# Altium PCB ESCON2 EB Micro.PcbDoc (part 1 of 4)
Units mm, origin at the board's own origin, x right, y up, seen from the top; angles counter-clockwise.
Board outline 75.6 x 72 mm, 8 copper layers (Top Side, Mid Layer 1, Mid Layer 2, Mid Layer 3, Mid Layer 4, Mid Layer 5, Mid Layer 6, Bottom Side), stack 1.555 mm thick; 192 components, 85 nets, 547 pads, 2387 vias.
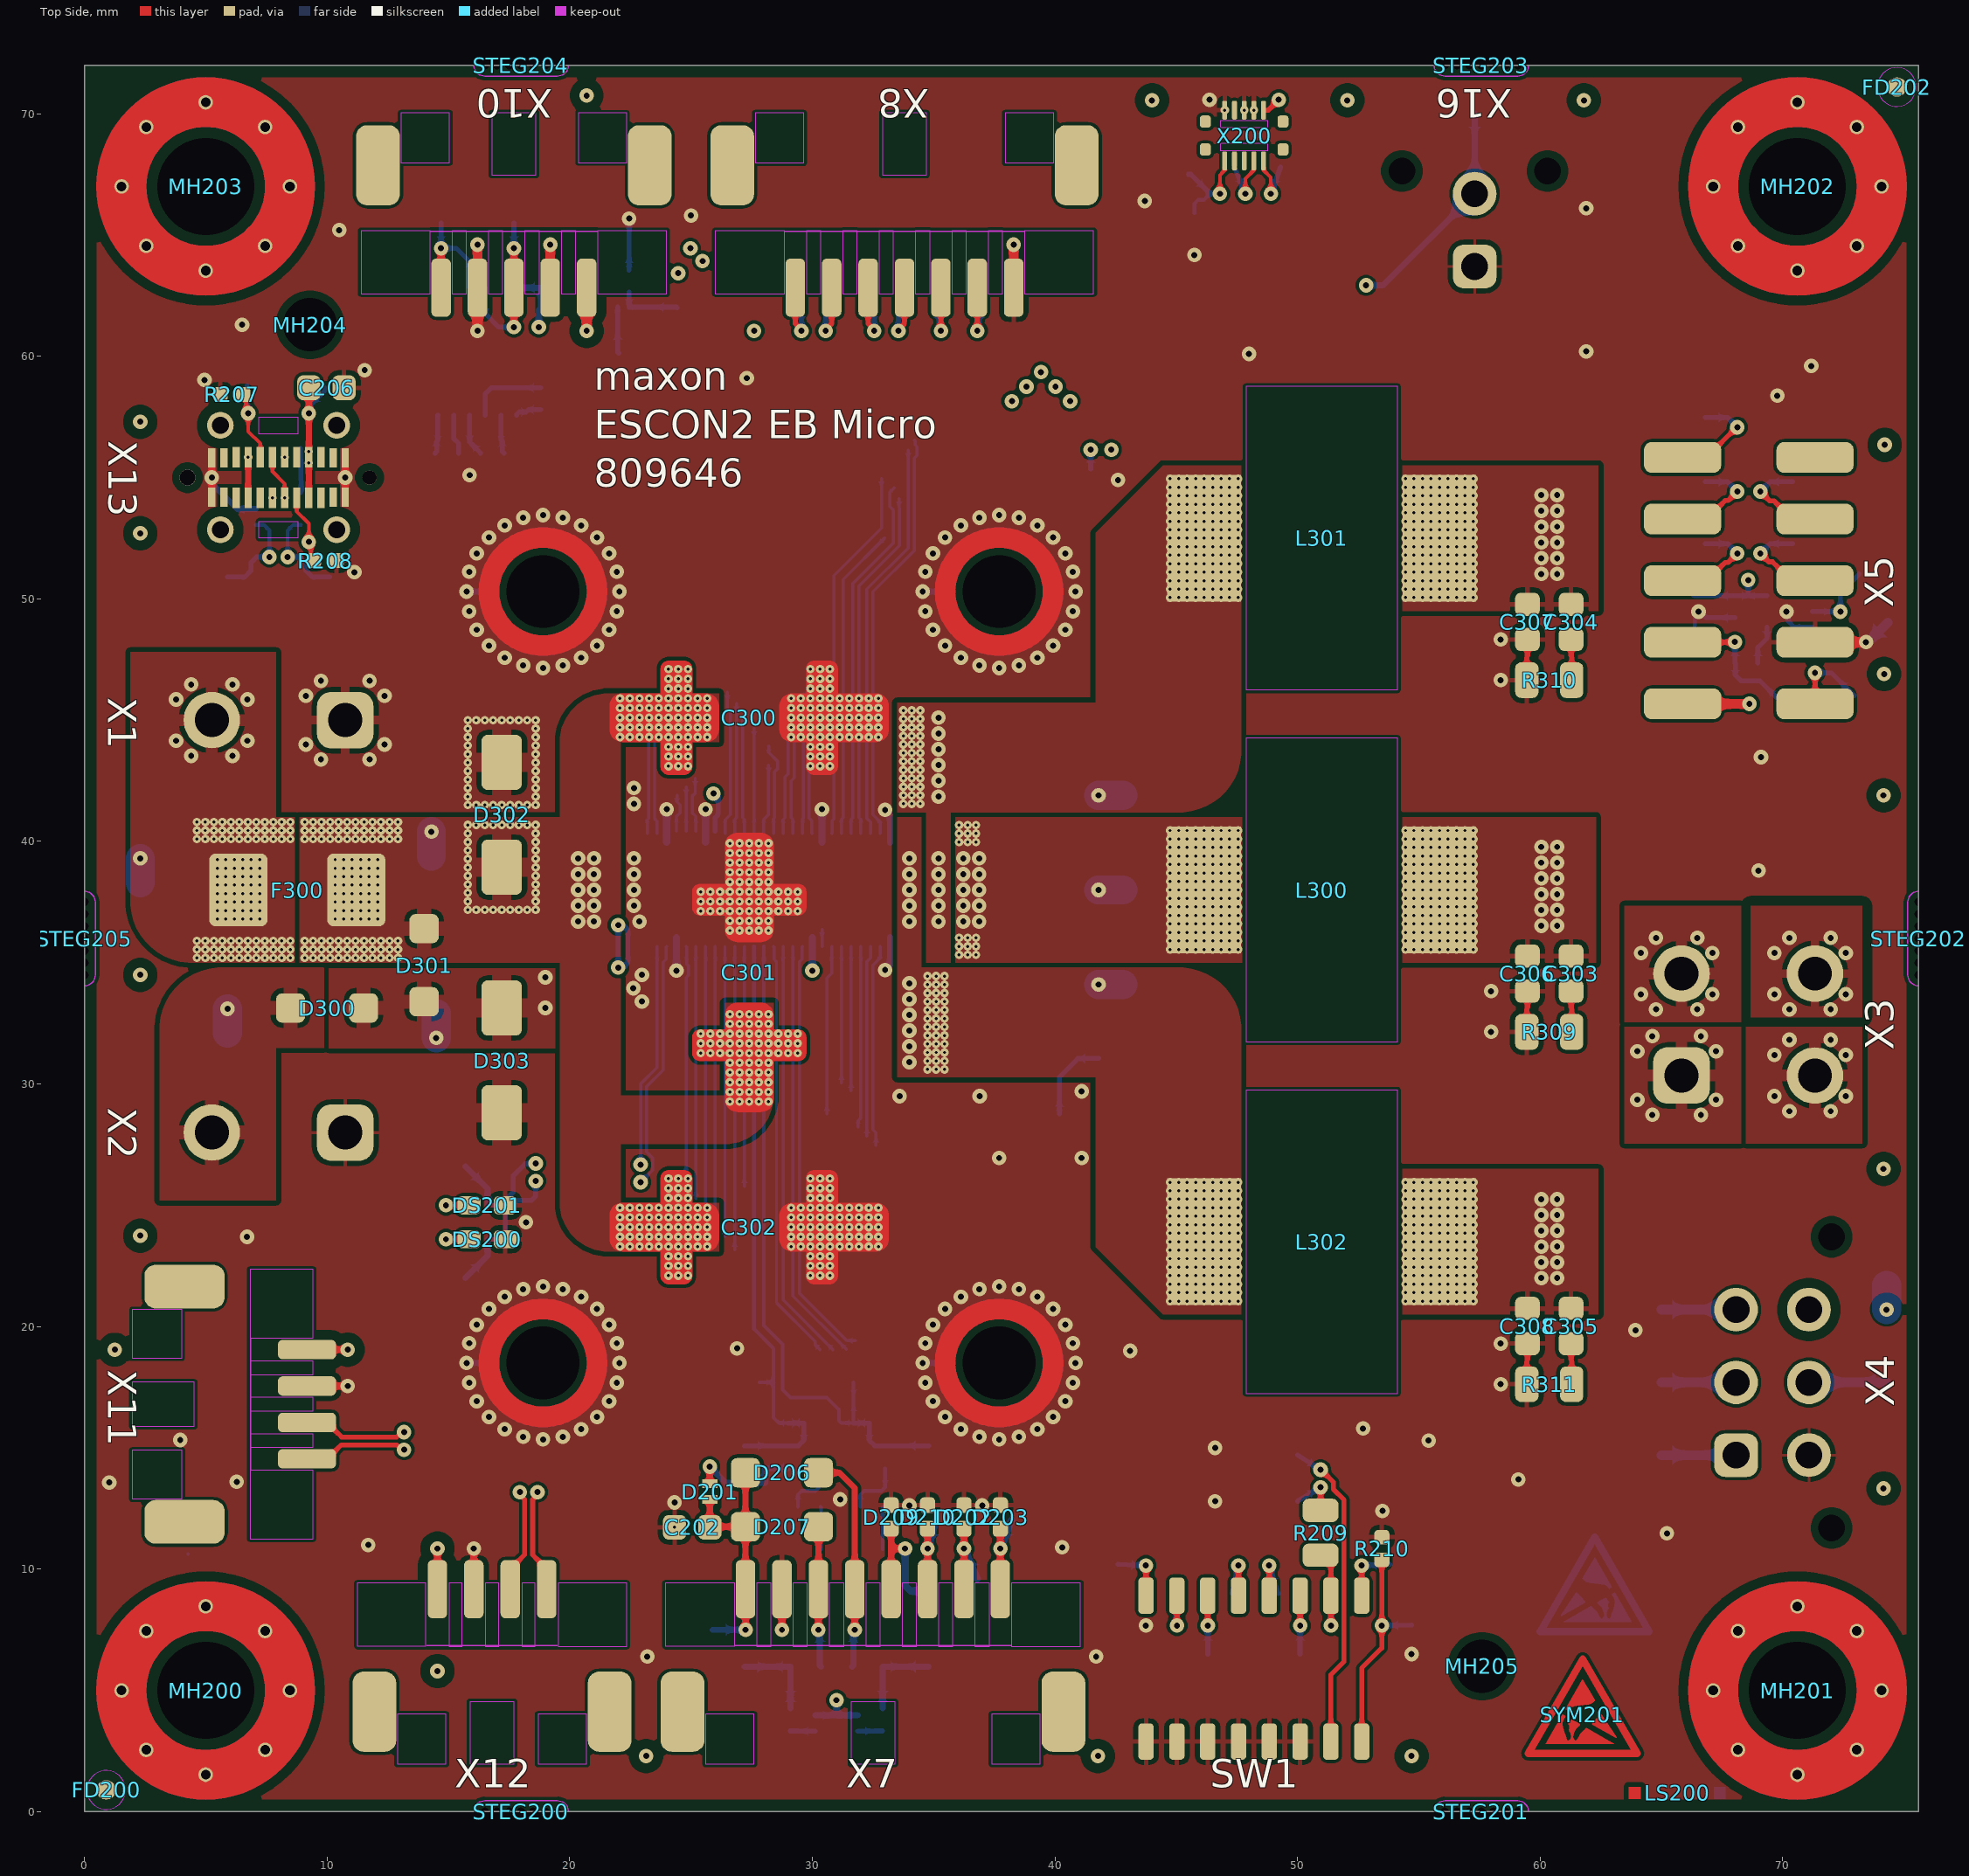
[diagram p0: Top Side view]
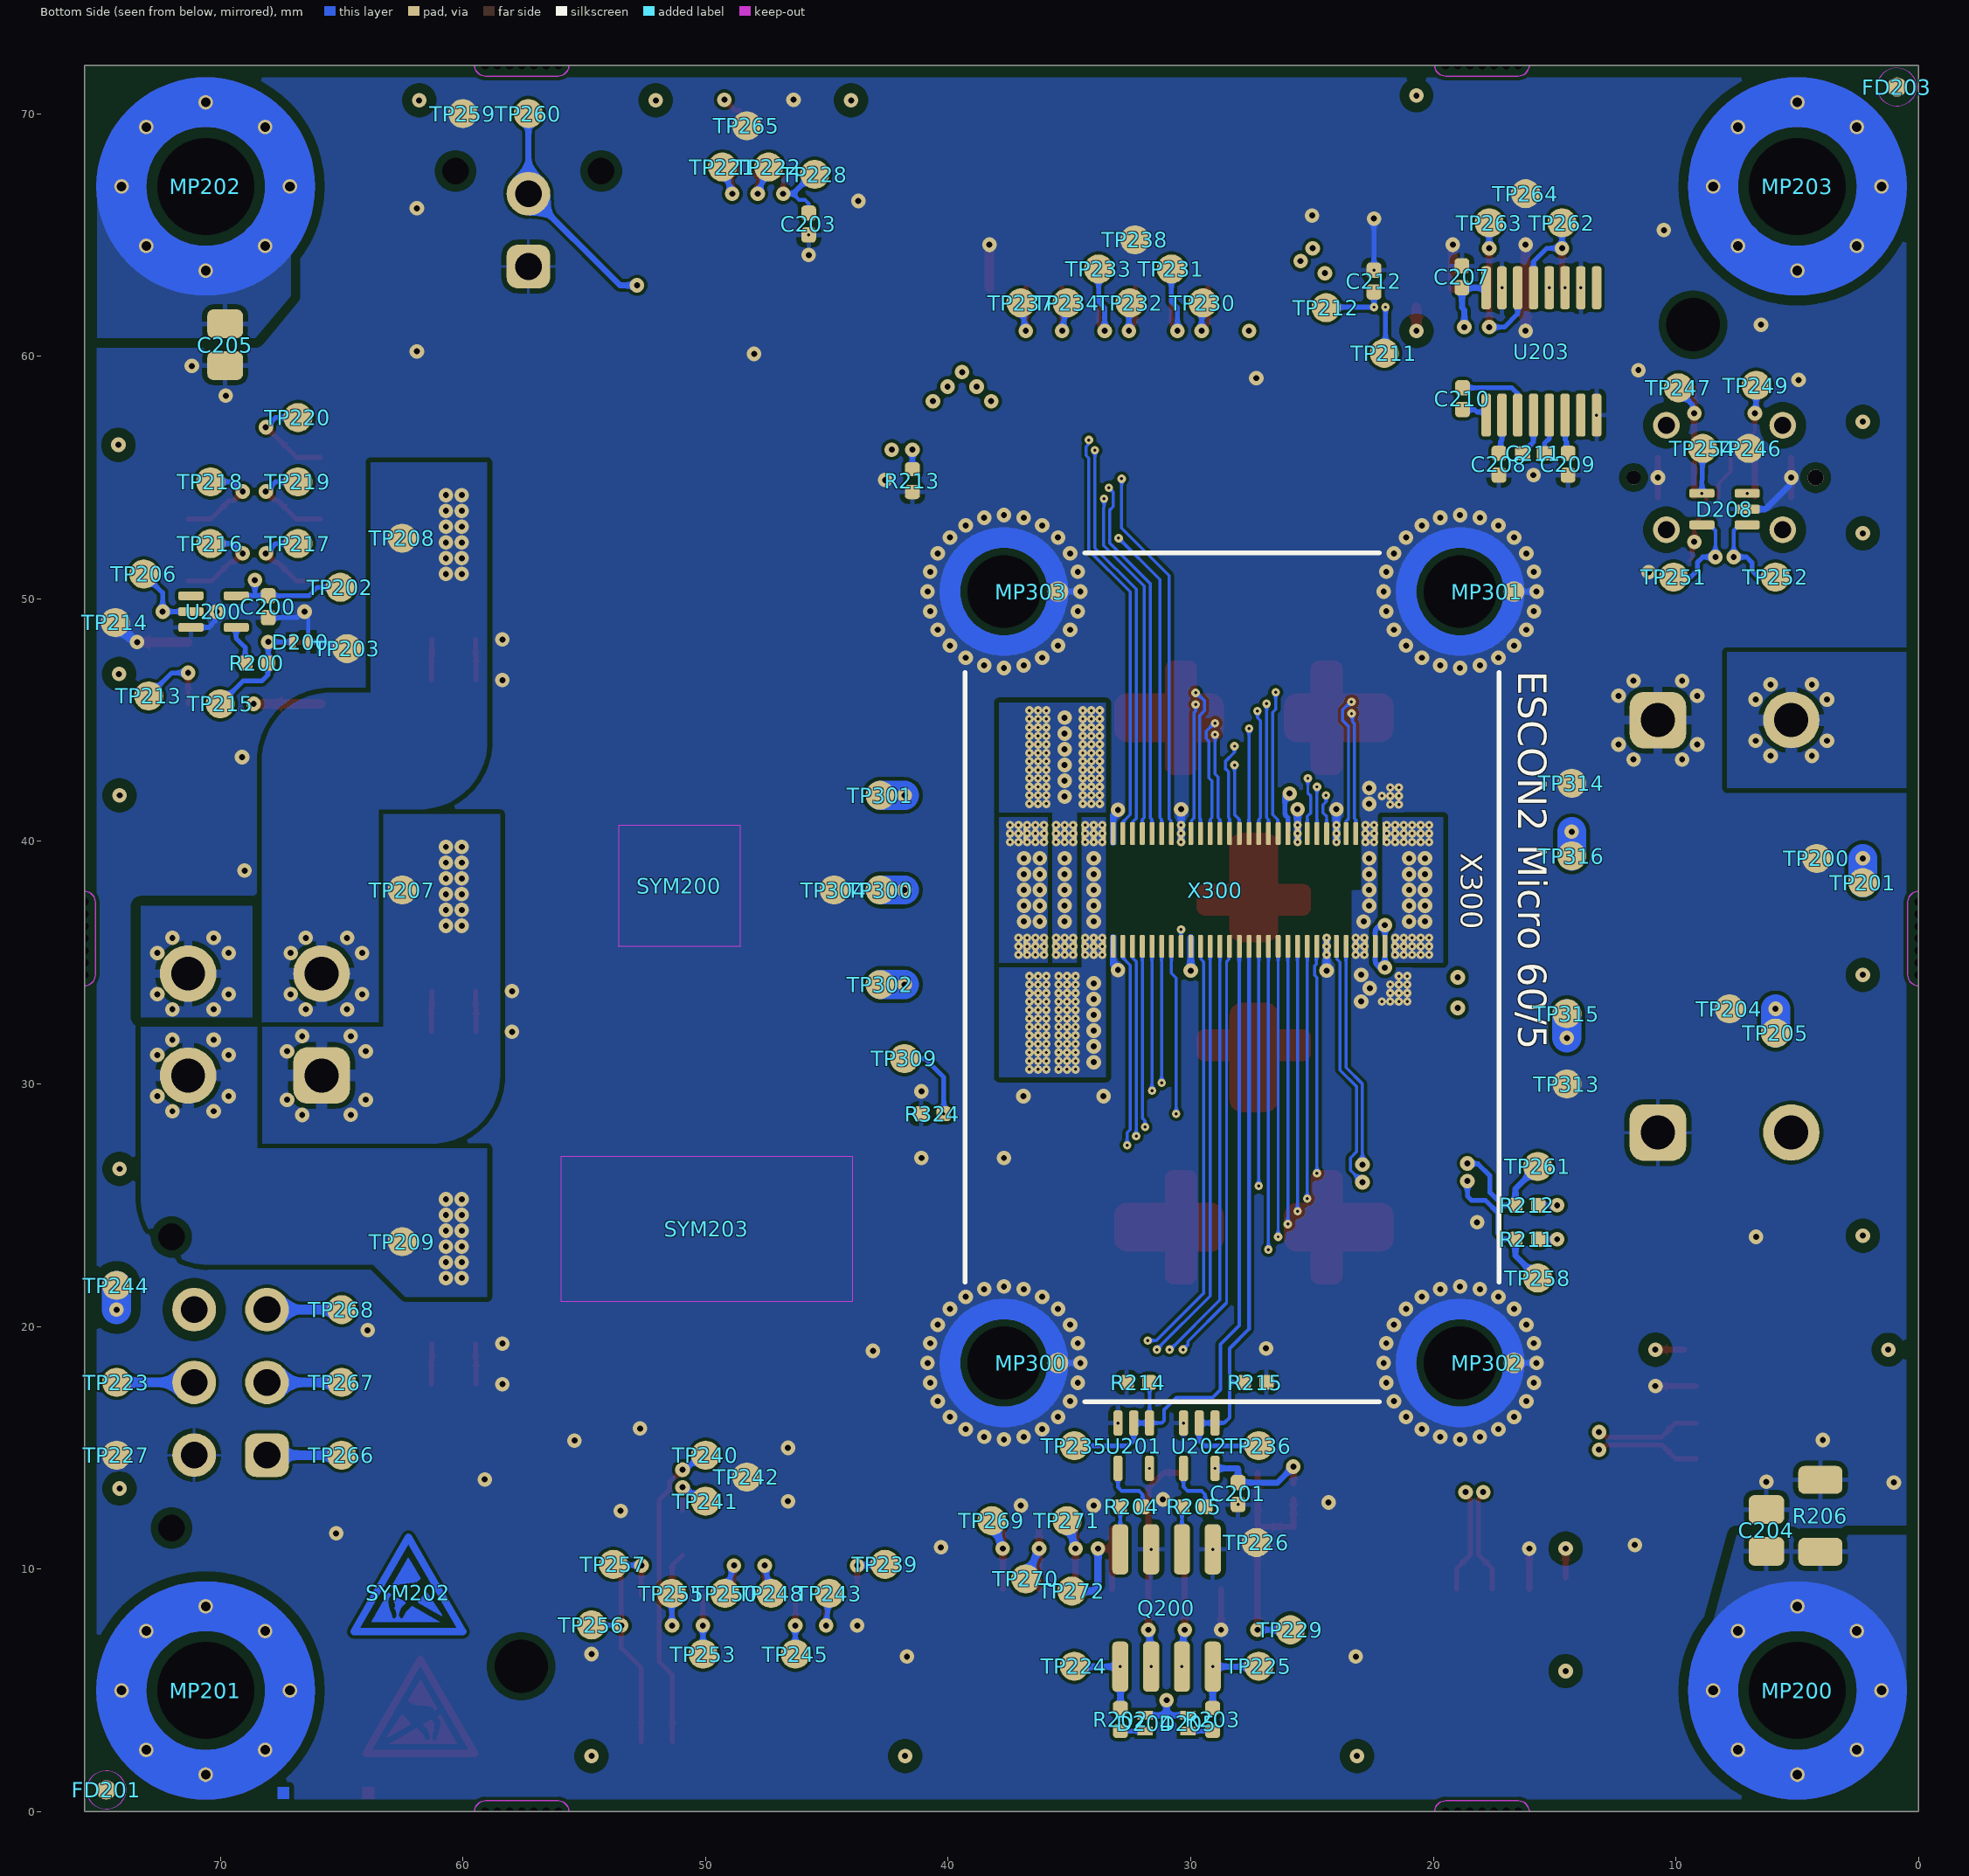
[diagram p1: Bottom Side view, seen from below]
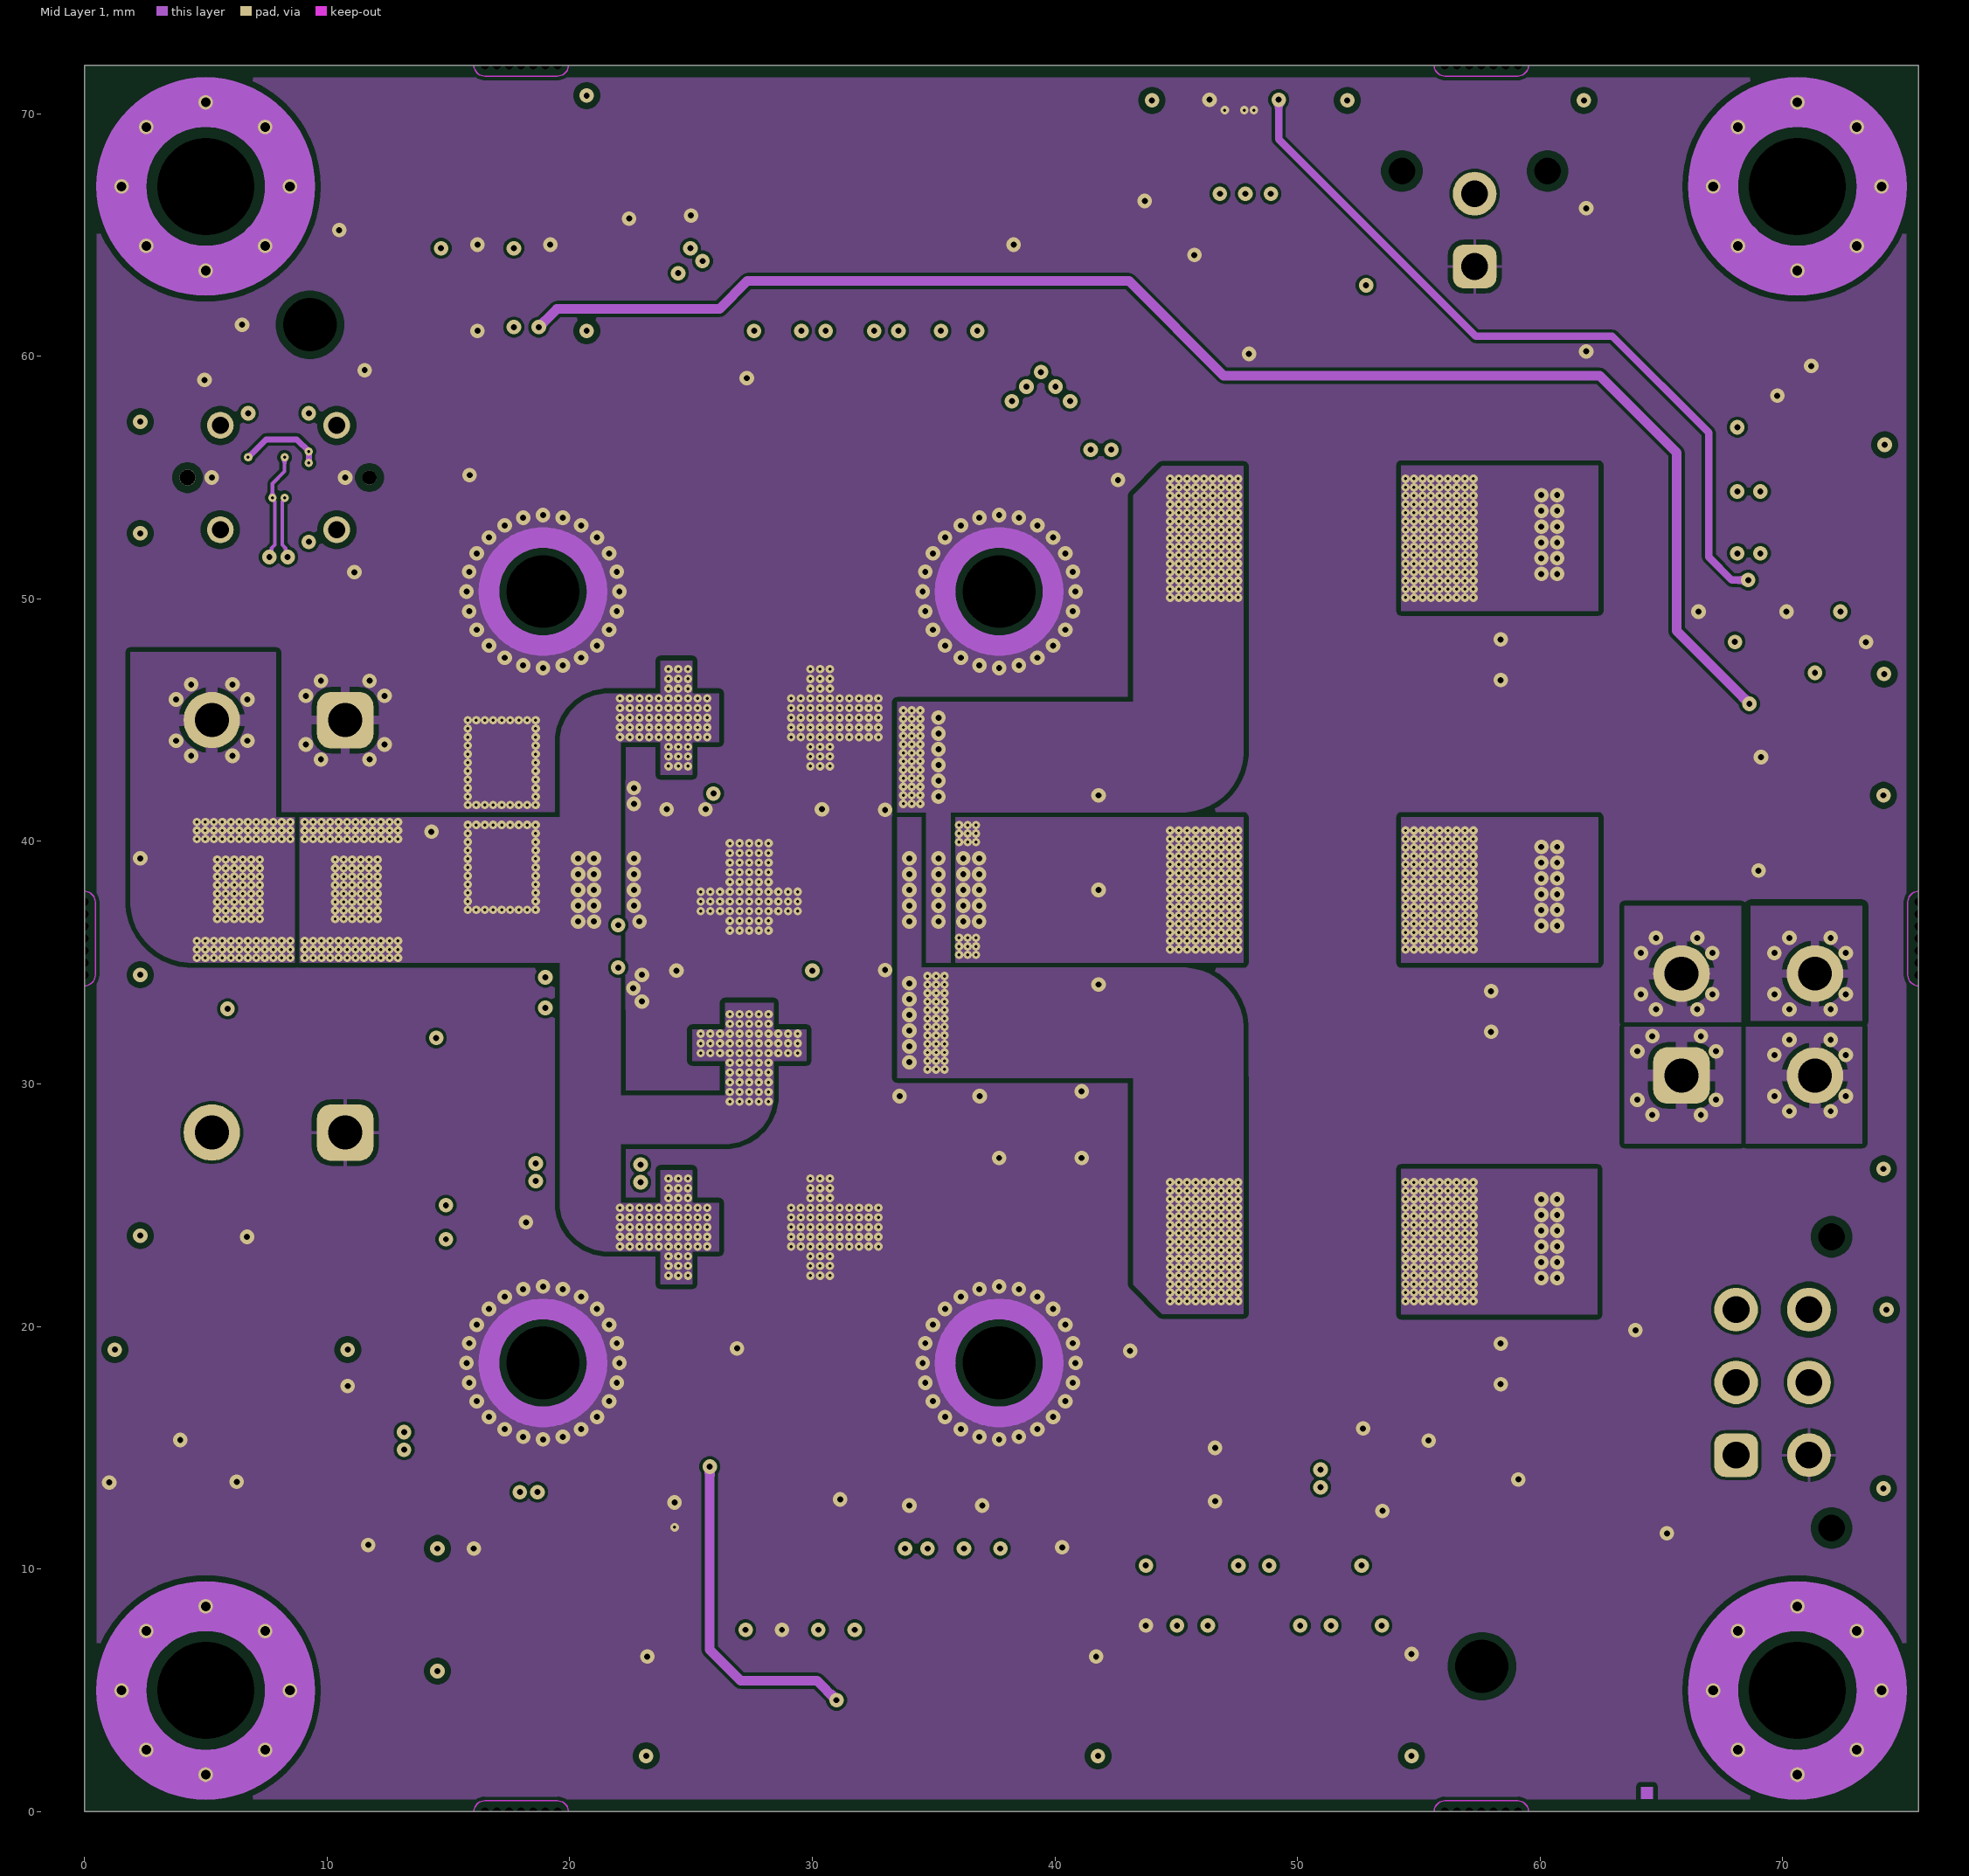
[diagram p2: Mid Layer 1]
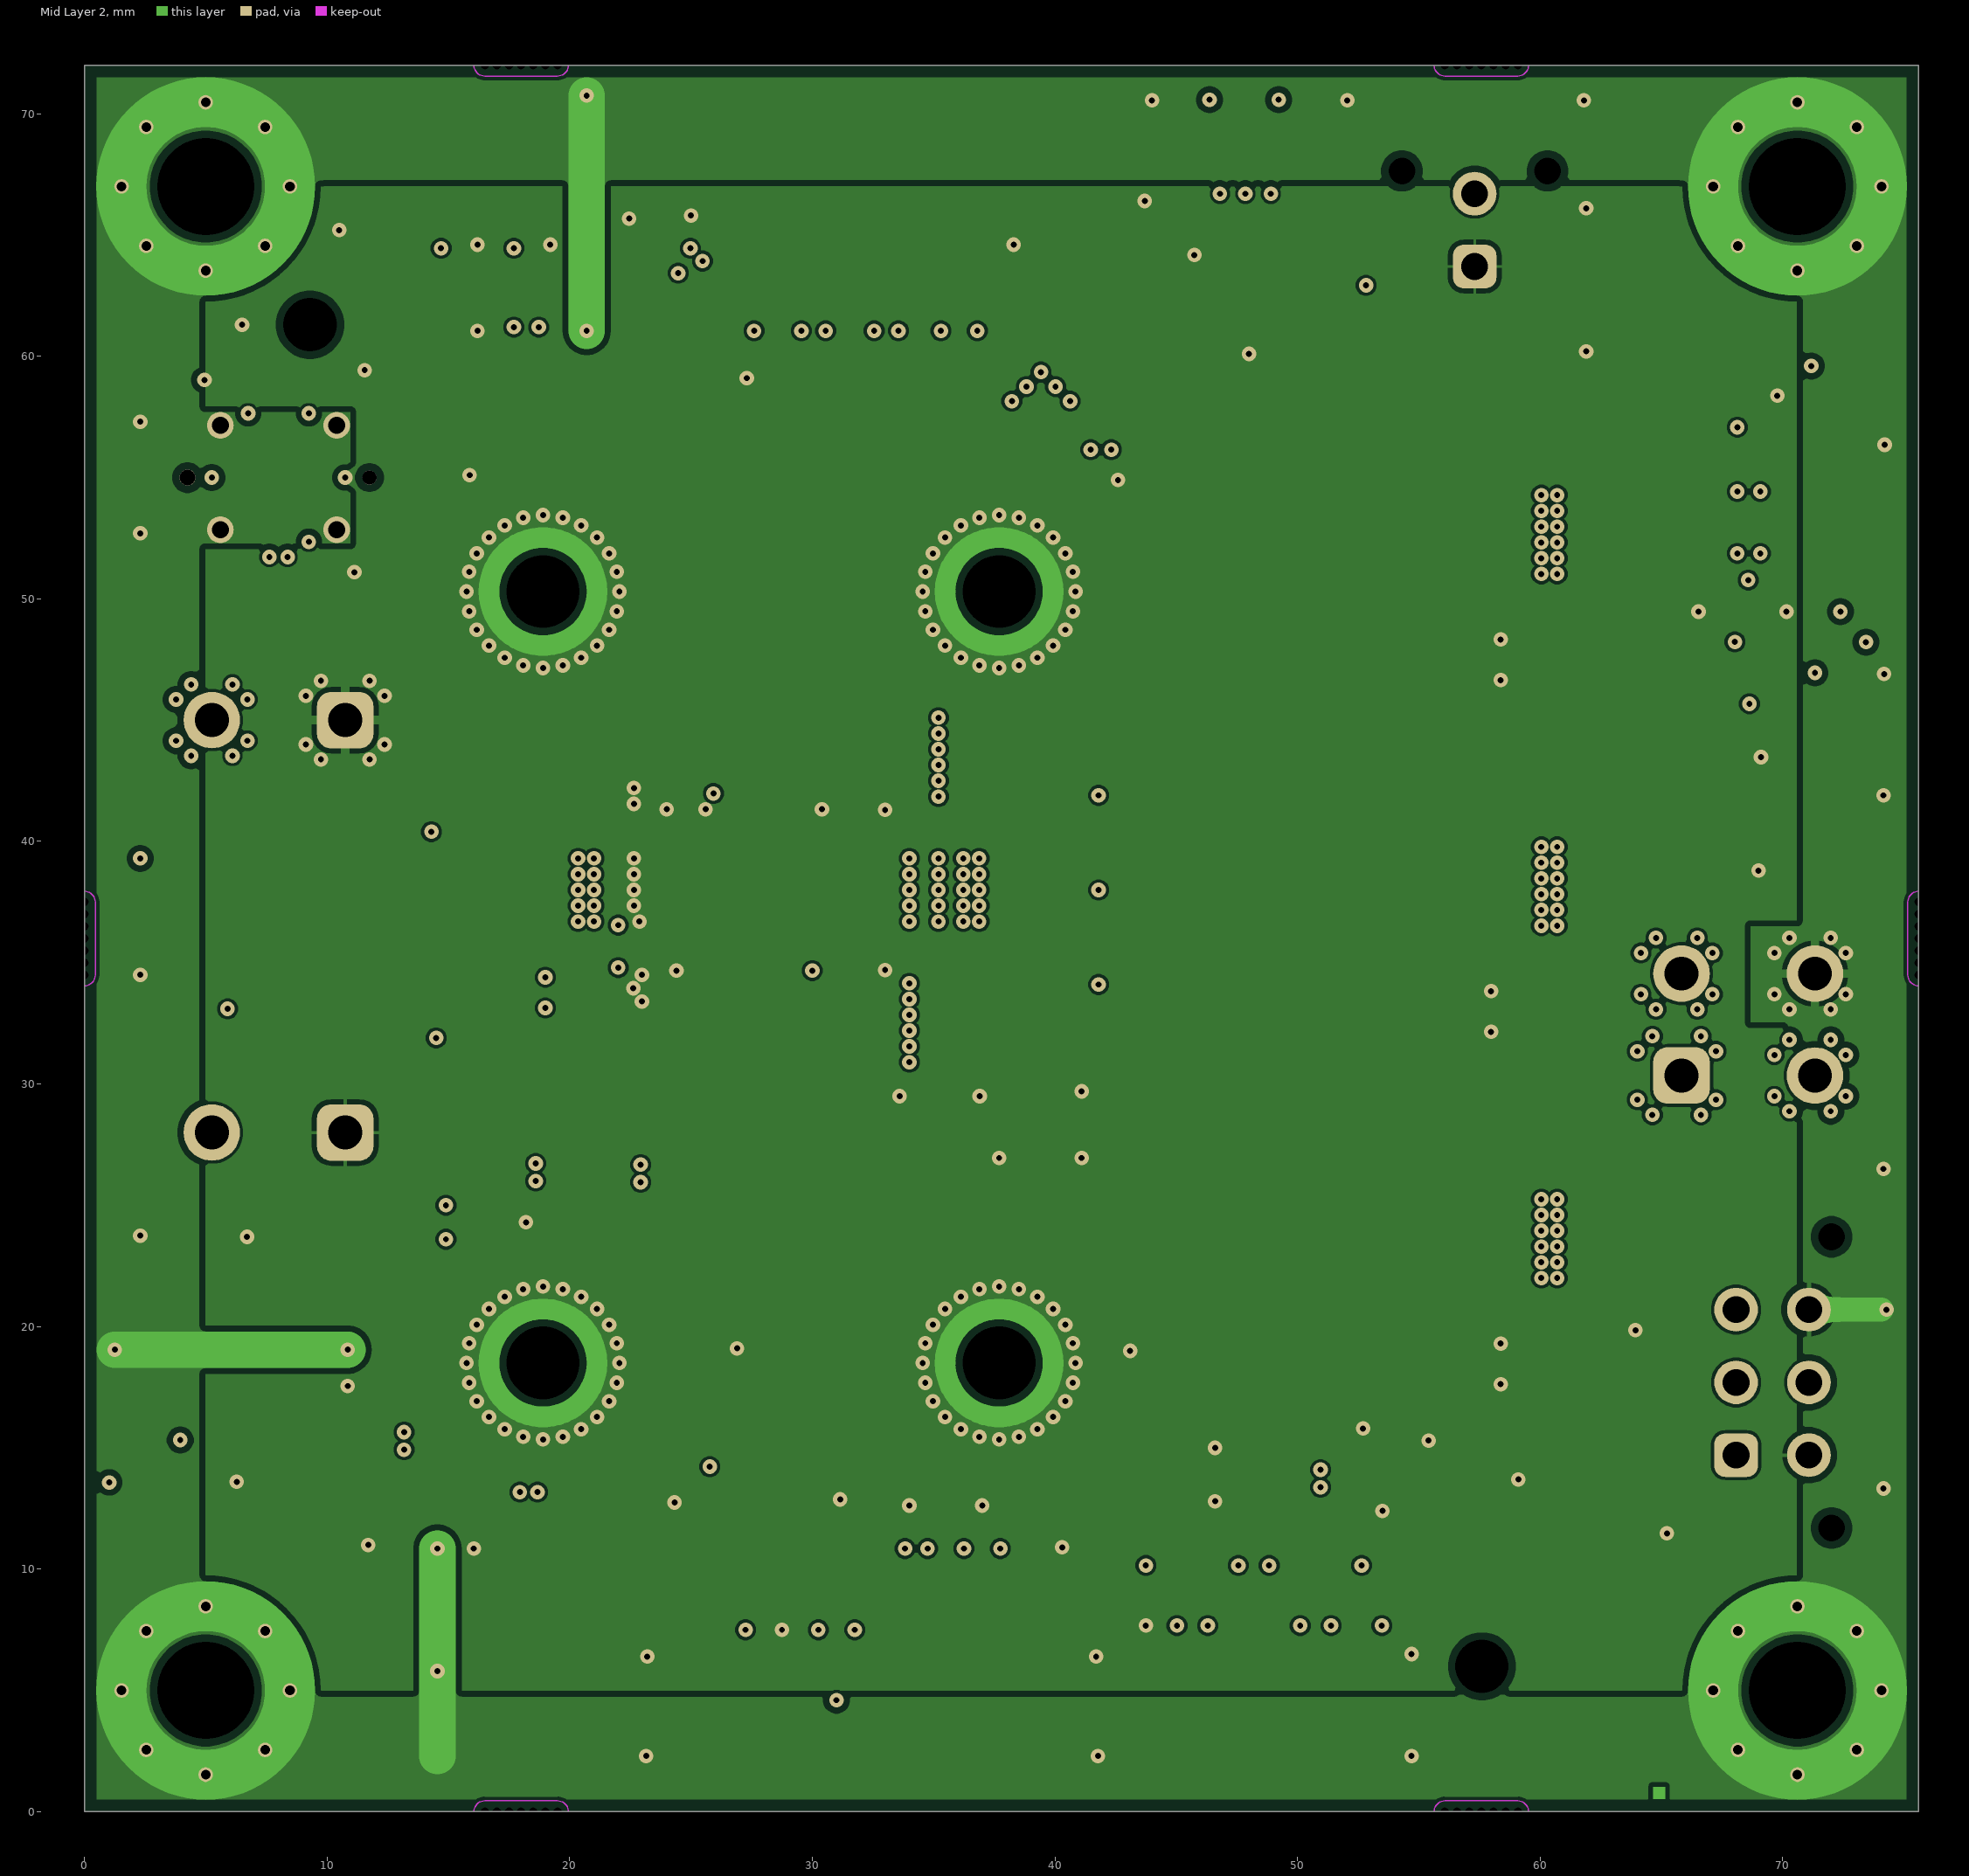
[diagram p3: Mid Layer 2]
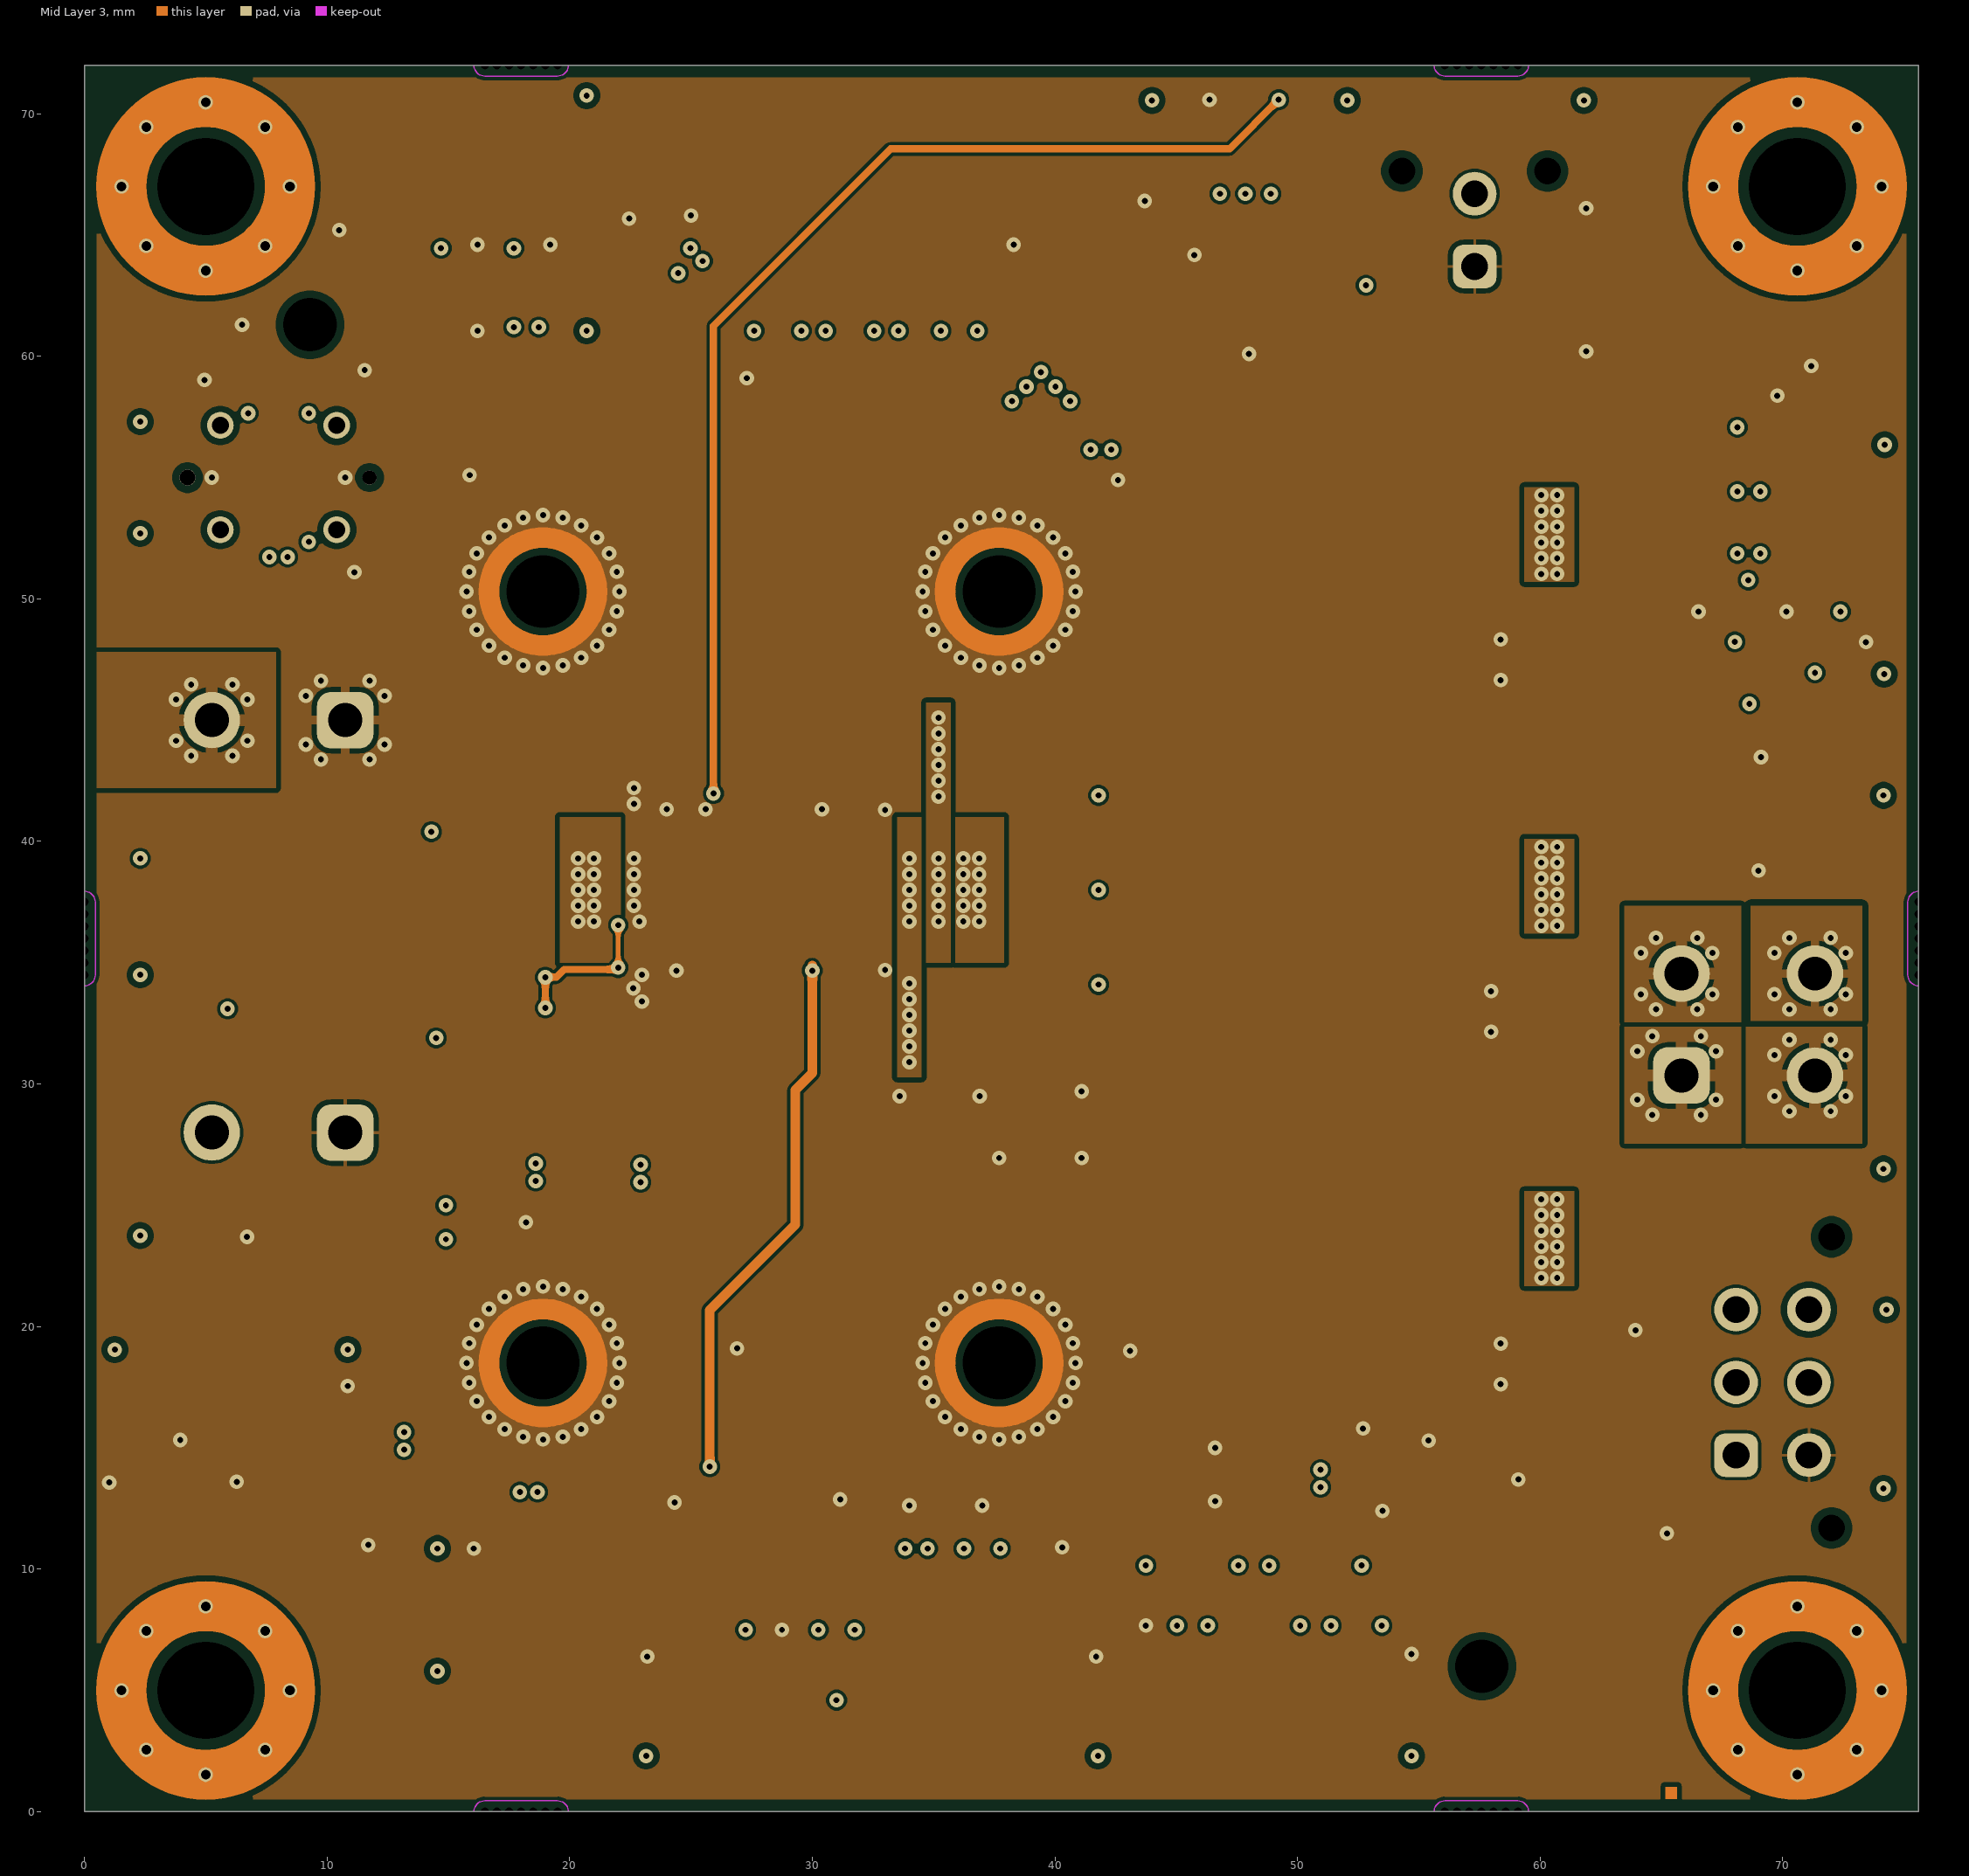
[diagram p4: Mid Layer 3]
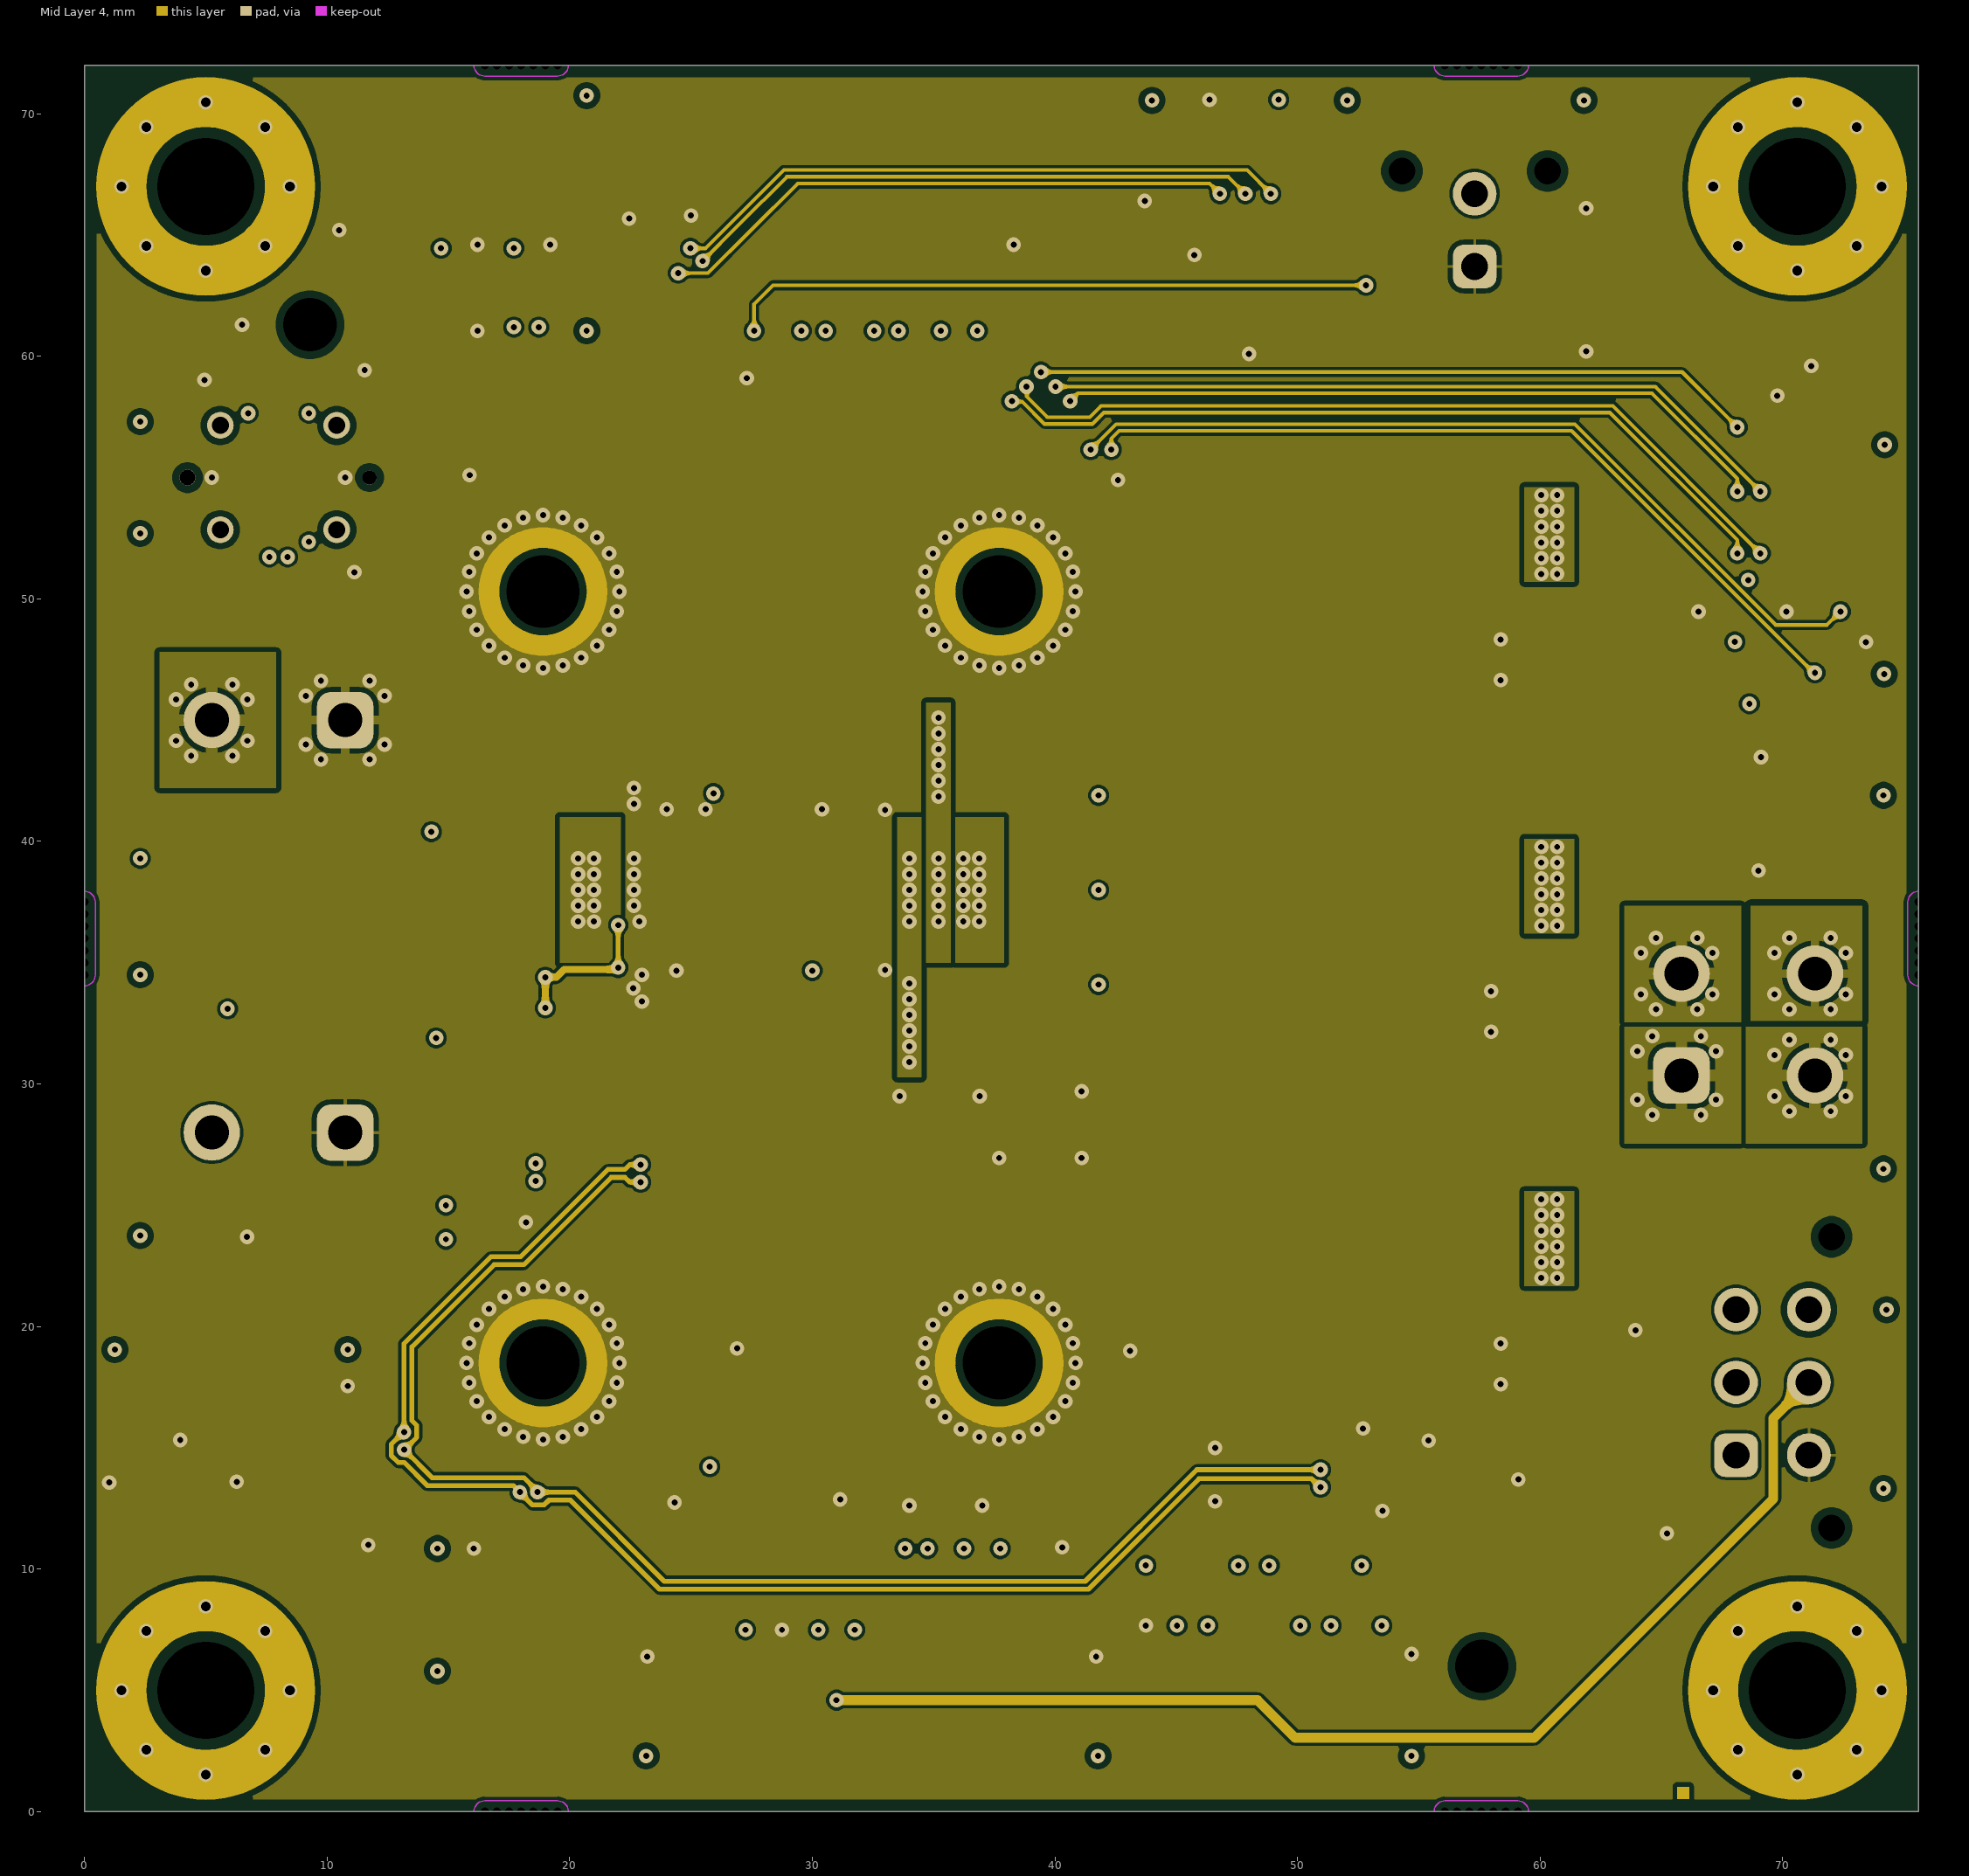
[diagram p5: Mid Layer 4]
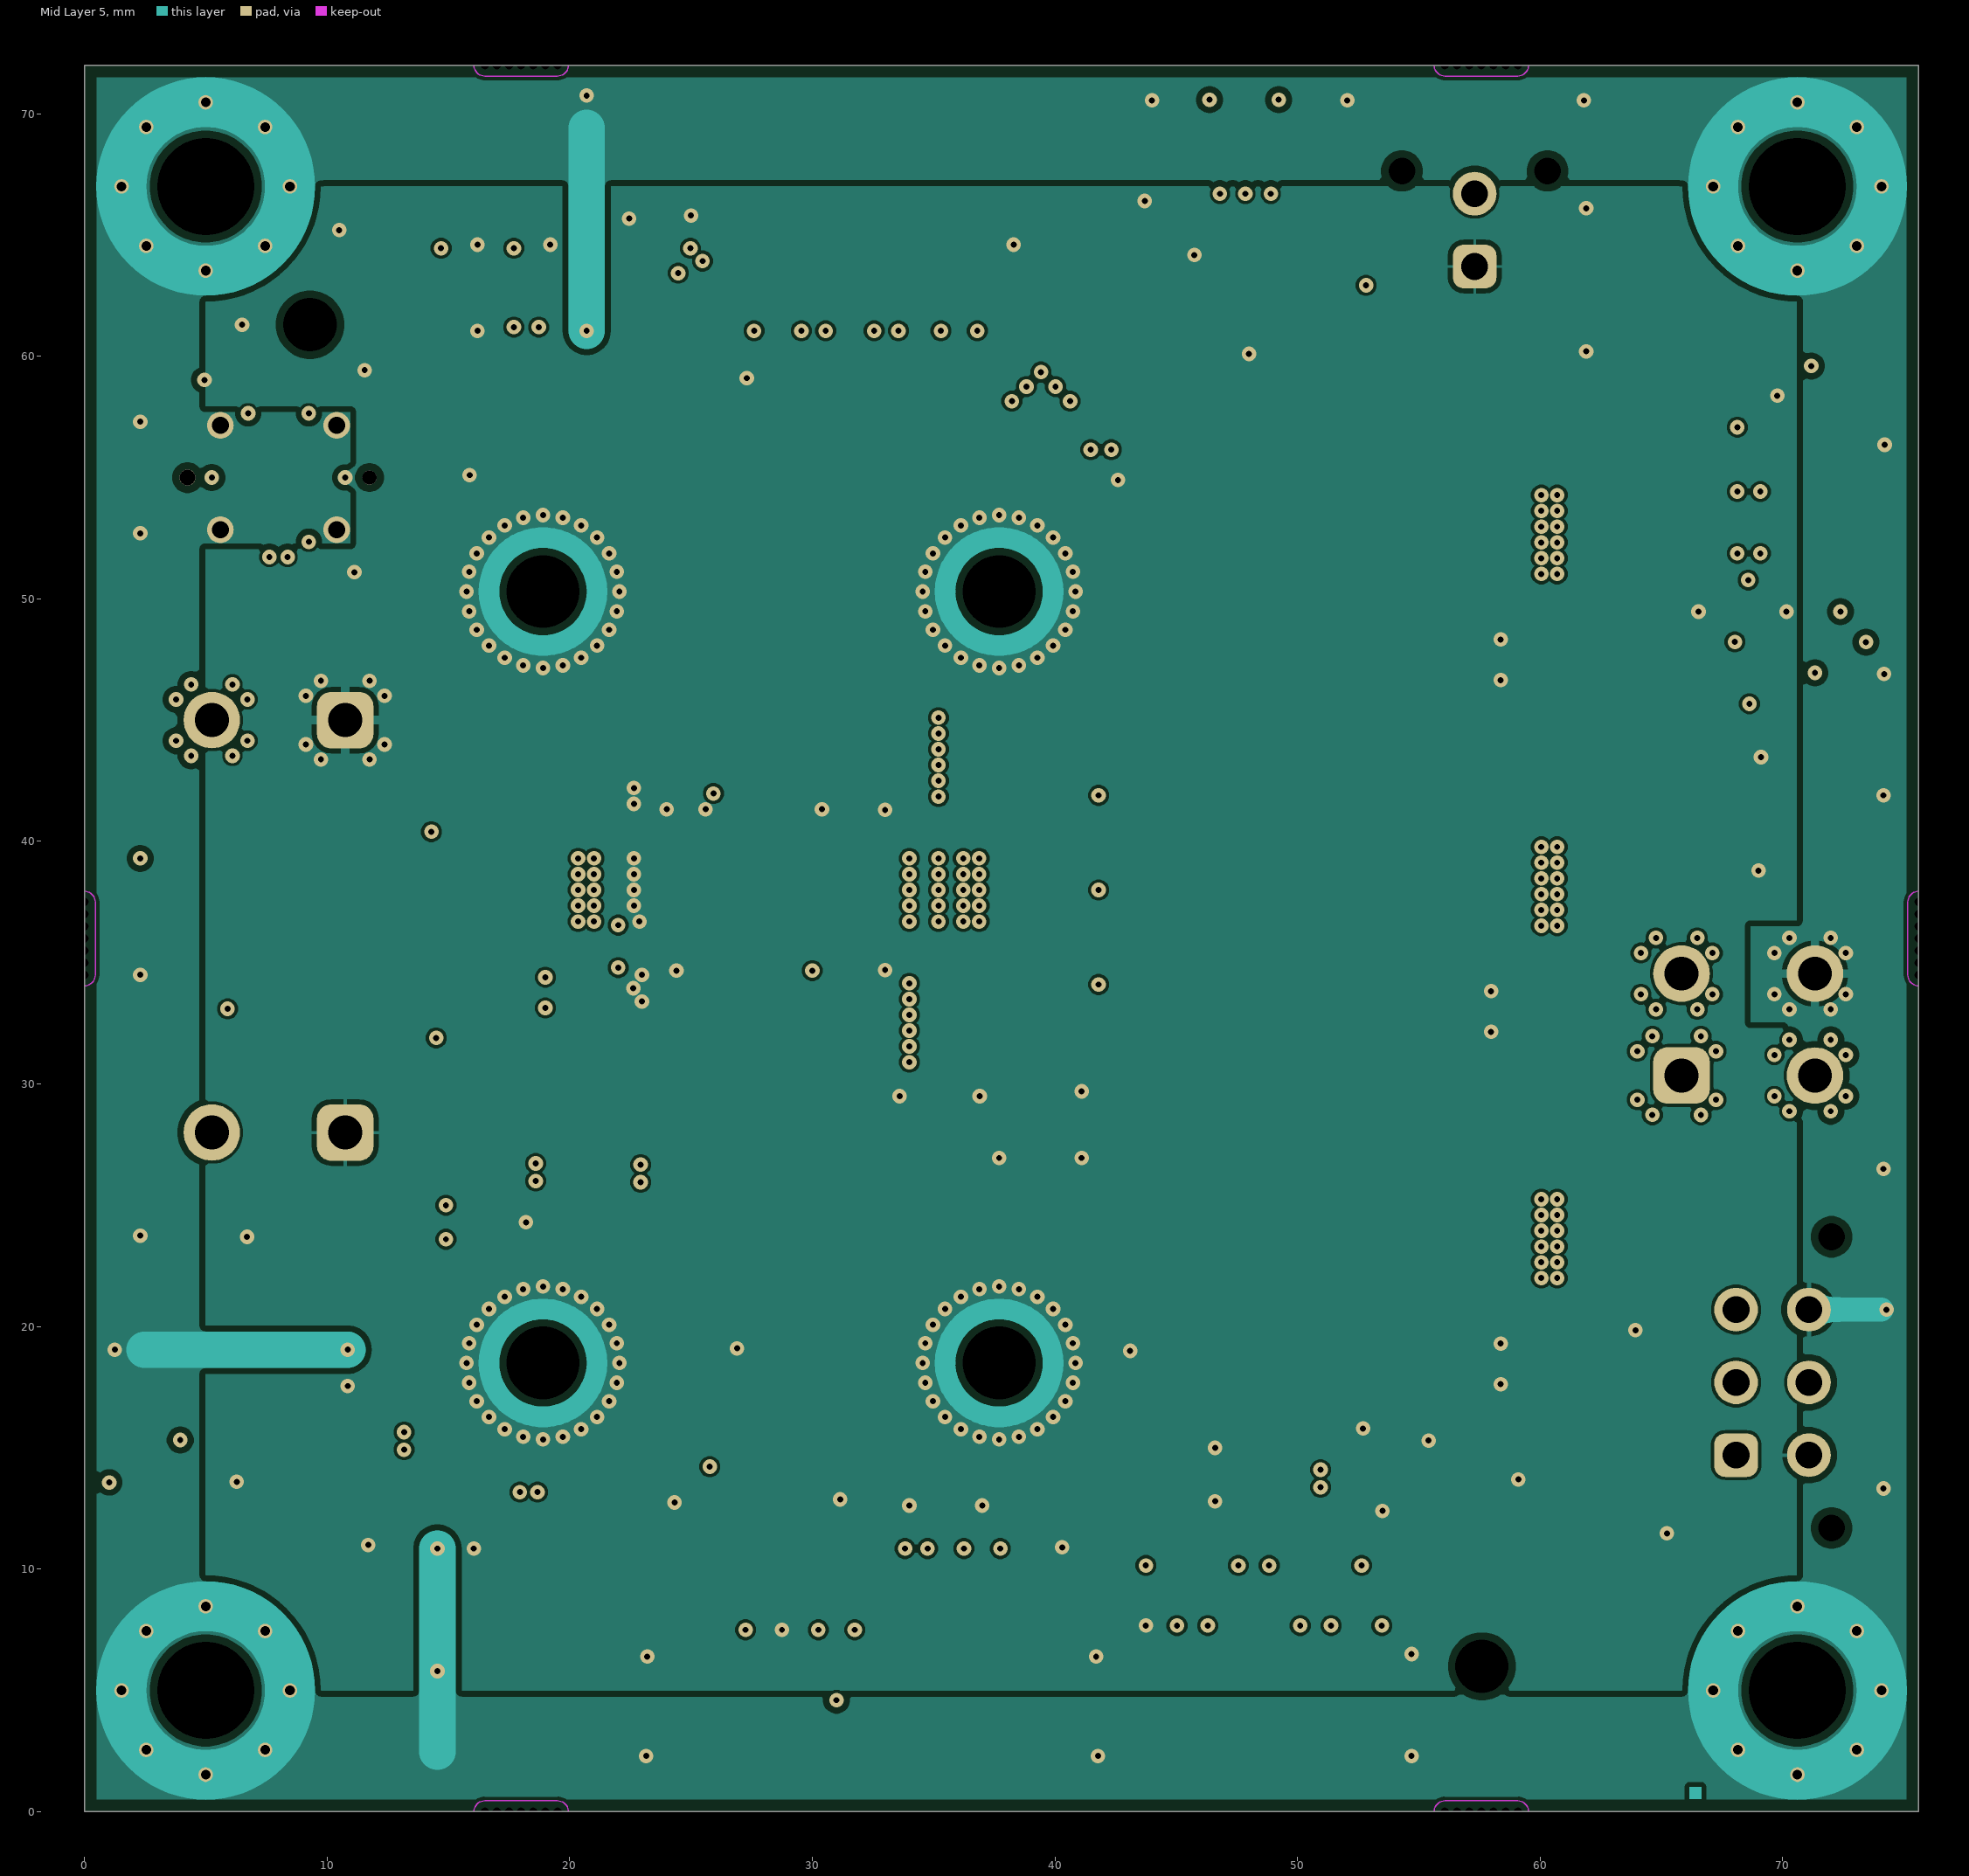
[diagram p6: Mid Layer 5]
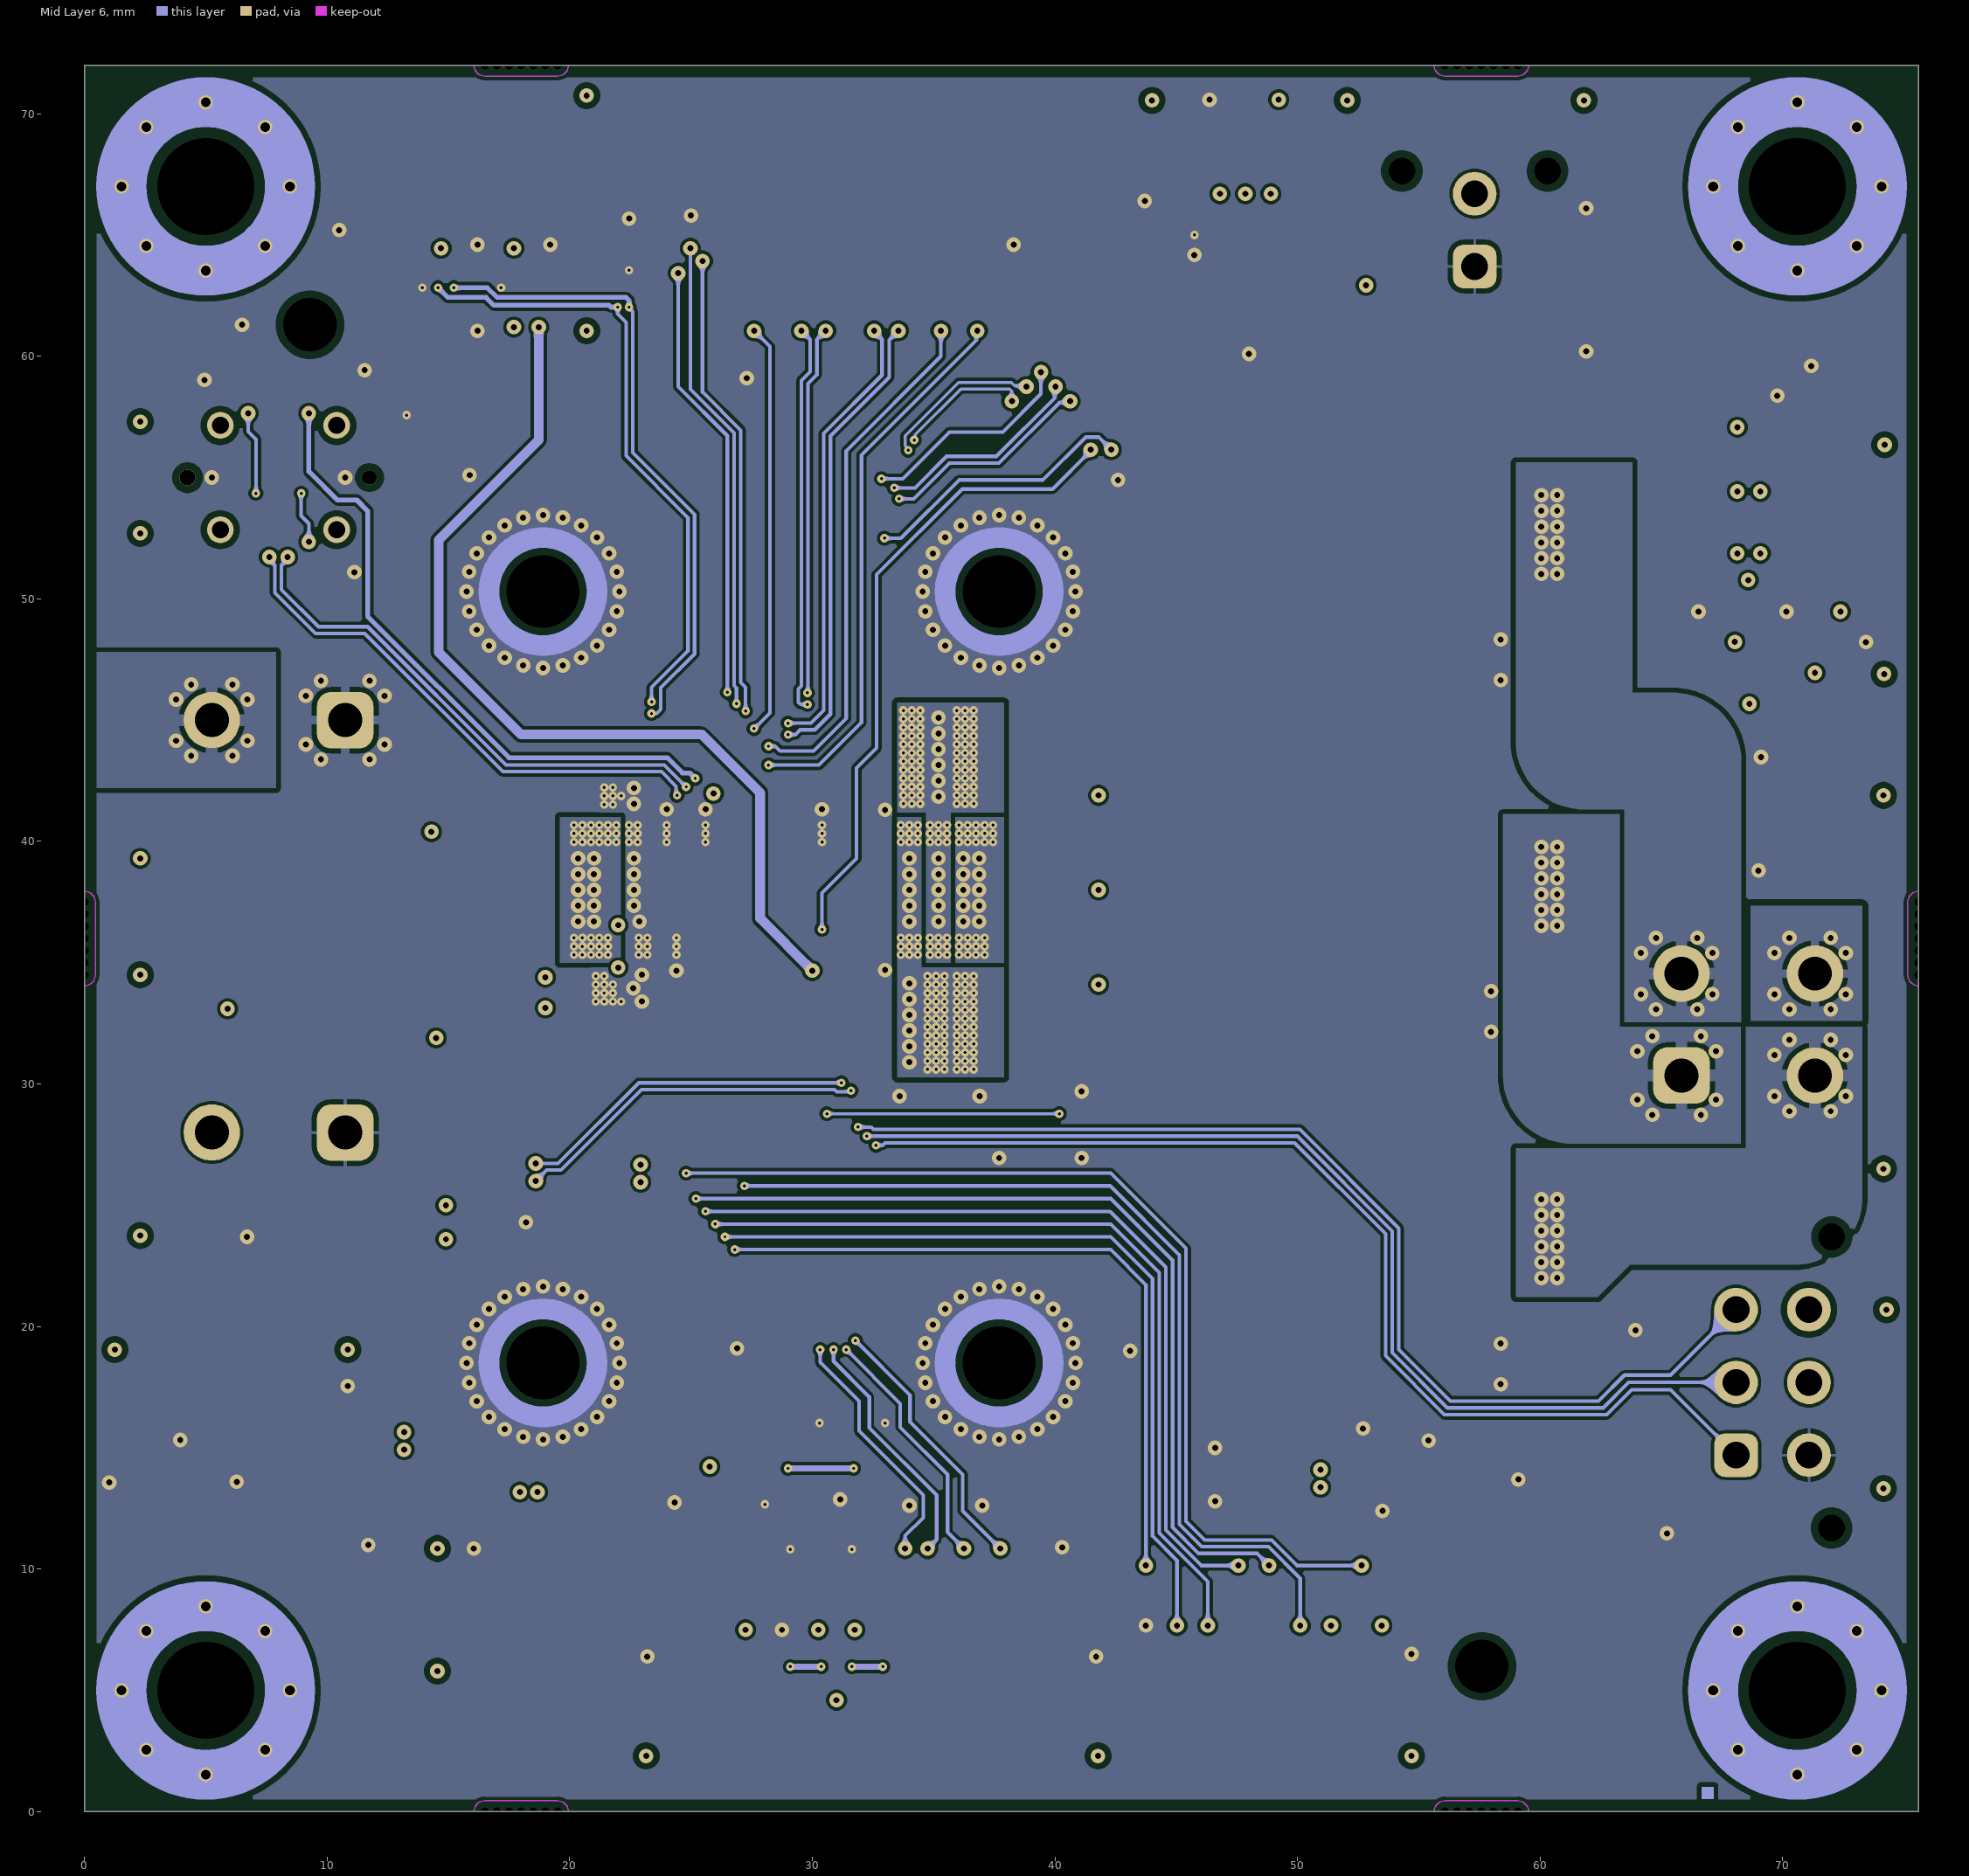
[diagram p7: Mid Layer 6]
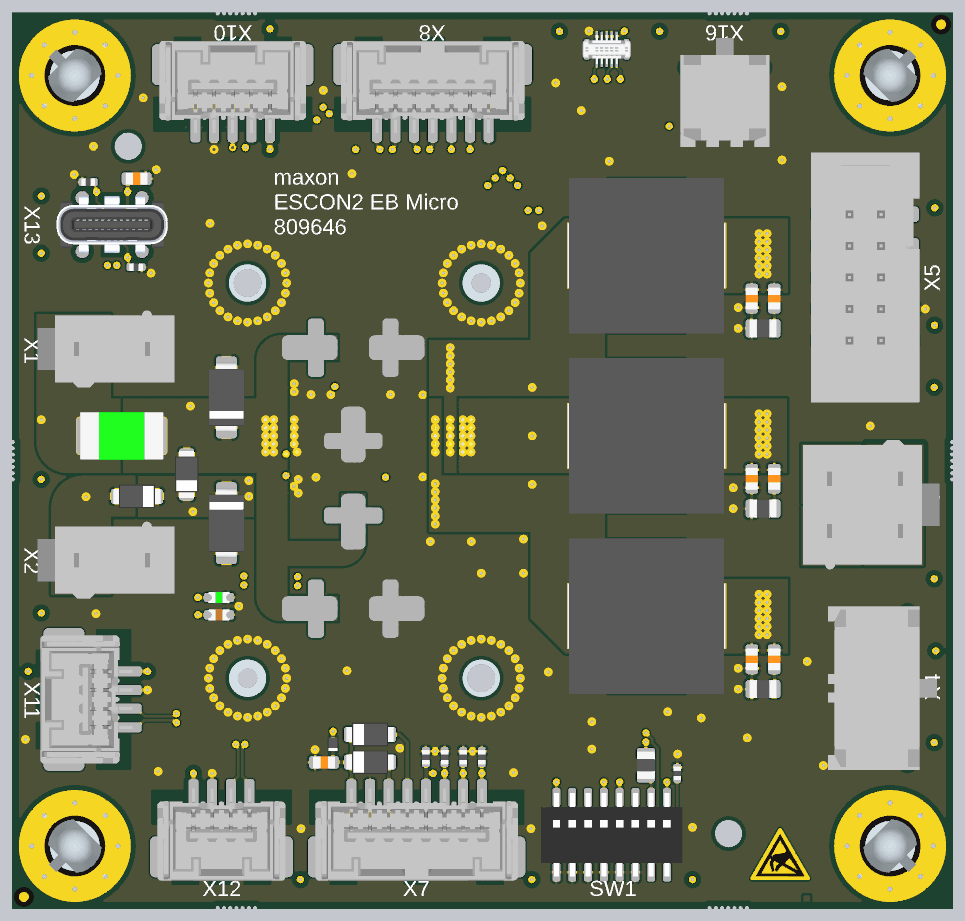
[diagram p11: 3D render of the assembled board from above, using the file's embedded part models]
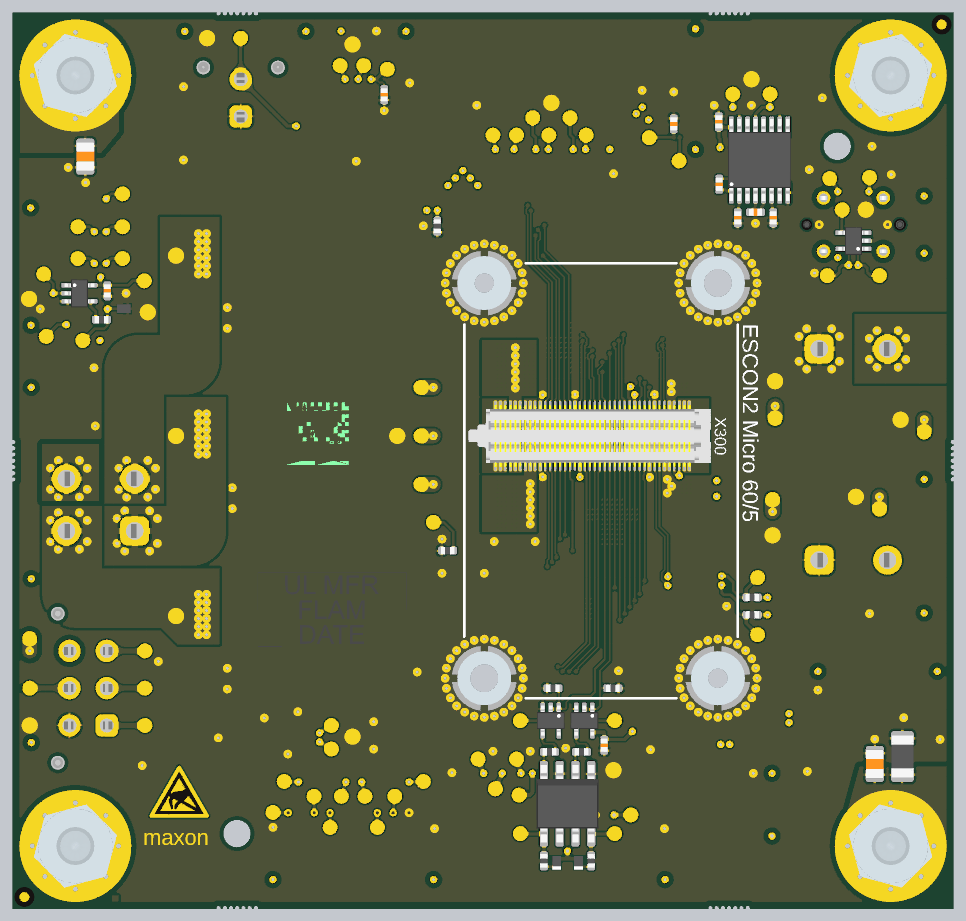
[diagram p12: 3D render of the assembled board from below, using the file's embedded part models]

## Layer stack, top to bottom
Top Solder: solder mask 0.015, Dk 3.5
Top Side: signal copper 0.03
Dielectric 1: prepreg 0.065, Dk 3.5
Mid Layer 1: signal copper 0.035
Core 1: core 0.3, Dk 4.5
Mid Layer 2: signal copper 0.035
Dielectric 2: prepreg 0.125, Dk 3.7
Mid Layer 3: signal copper 0.035
Core 2: core 0.3, Dk 4.5
Mid Layer 4: signal copper 0.035
Dielectric 3: prepreg 0.125, Dk 3.7
Mid Layer 5: signal copper 0.035
Core 3: core 0.3, Dk 4.5
Mid Layer 6: signal copper 0.035
Dielectric 4: prepreg 0.065, Dk 3.5
Bottom Side: signal copper 0.035
Bottom Solder: solder mask 0.015, Dk 3.5

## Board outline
0,0 0,72 75.6,72 75.6,0

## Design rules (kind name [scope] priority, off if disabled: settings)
AssemblyTestPointUsage [All] p1: valid=2
AssemblyTestpoint [All] p1: testpointundercomponent=TRUE minsize=1 maxsize=2 preferedsize=1 minholesize=0 maxholesize=0 preferedholesize=0 testpointgrid=0.05 usegrid=FALSE gridoriginx=120 gridoriginy=100 gridtolerance=0 allowsidebottom=TRUE minspacing=1.9 padholecenterclearance=0.6
BoardOutlineClearance BOC_Overlay [OnLayer('Top Designator') OR OnLayer('Bottom Designator')] p1: gap=0 ignorepadtopadclearanceinfootprint=FALSE
BoardOutlineClearance BOC_Text [isText] p2: gap=0 ignorepadtopadclearanceinfootprint=FALSE
BoardOutlineClearance BOC_Fiducials [InComponent('FD*')] p3: gap=0.1 ignorepadtopadclearanceinfootprint=FALSE
BoardOutlineClearance BOC_Steg [InComponent('STEG*')] p4: gap=0 ignorepadtopadclearanceinfootprint=FALSE
BoardOutlineClearance BOC_Keepout [IsKeepout] p5: gap=0 ignorepadtopadclearanceinfootprint=FALSE
BoardOutlineClearance BOC_All [All] p6: gap=0.5 ignorepadtopadclearanceinfootprint=FALSE
Clearance C_NPTHtoAll [(ObjectKind = 'Pad') AND (Layer = 'MultiLayer') AND (PadIsPlated = 'False') AND NOT HasFootprint('Steg*')] p1: gap=0.3 ignorepadtopadclearanceinfootprint=FALSE
Clearance C_LStoAll [InComponent('LS*')] p2: gap=0.2 ignorepadtopadclearanceinfootprint=FALSE
Clearance C_NetSGNDtoAll_onOutside [InNet('SGND') AND ( ExistsOnLayer('Top Side') OR ExistsOnLayer('Bottom Side') ) vs ExistsOnLayer('Top Side') OR ExistsOnLayer('Bottom Side')] p3: gap=0.4 ignorepadtopadclearanceinfootprint=FALSE
Clearance C_NetSGNDtoAll_onMid [InNet('SGND') AND ( ExistsOnLayer('Mid Layer 1') OR ExistsOnLayer('Mid Layer 2') OR ExistsOnLayer('Mid Layer 3') OR ExistsOnLayer('Mid Layer 4') OR ExistsOnLayer('Mid Layer 5') OR ExistsOnLayer('Mid Layer 6') OR ExistsOnLayer('Mid Layer 7') OR ExistsOnLayer('Mid Layer 8') OR ExistsOnLayer('Mid Layer 9') OR ExistsOnLayer('Mid Layer 10') ) vs ExistsOnLayer('Mid Layer 1') OR ExistsOnLayer('Mid Layer 2') OR ExistsOnLayer('Mid Layer 3') OR ExistsOnLayer('Mid Layer 4') OR ExistsOnLayer('Mid Layer 5') OR ExistsOnLayer('Mid Layer 6') OR ExistsOnLayer('Mid Layer 7') OR ExistsOnLayer('Mid Layer 8') OR ExistsOnLayer('Mid Layer 9') OR ExistsOnLayer('Mid Layer 10')] p4: gap=0.25 ignorepadtopadclearanceinfootprint=FALSE except(0.3: Arc-Hole Track-Hole SMDPad-Hole THPad-Hole Via-Hole Fill-Hole Poly-Hole Region-Hole Text-Hole)
Clearance C_ClassHVtoPolygon [InPolygon and InNetClass('HV') vs InPolygon] p5: gap=0.2 ignorepadtopadclearanceinfootprint=FALSE
Clearance C_ClassNVtoPolygon [InPolygon and InNetClass('NV') vs InPolygon] p6: gap=0.15 ignorepadtopadclearanceinfootprint=FALSE
Clearance C_PolygonPolygon [InPolygon vs InPolygon] p7: gap=0.15 ignorepadtopadclearanceinfootprint=FALSE
Clearance C_ClassHVtoAll_onOutside [InNetClass('HV') AND (ExistsOnLayer('Top Side') OR ExistsOnLayer('Bottom Side')) vs ExistsOnLayer('Top Side') OR ExistsOnLayer('Bottom Side')] p8: gap=0.15 ignorepadtopadclearanceinfootprint=FALSE
Clearance C_ClassHVtoAll_onMid [InNetClass('HV')  AND ( ExistsOnLayer('Mid Layer 1') OR ExistsOnLayer('Mid Layer 2') OR ExistsOnLayer('Mid Layer 3') OR ExistsOnLayer('Mid Layer 4') OR ExistsOnLayer('Mid Layer 5') OR ExistsOnLayer('Mid Layer 6') OR ExistsOnLayer('Mid Layer 7') OR ExistsOnLayer('Mid Layer 8') OR ExistsOnLayer('Mid Layer 9') OR ExistsOnLayer('Mid Layer 10') ) vs ExistsOnLayer('Mid Layer 1') OR ExistsOnLayer('Mid Layer 2') OR ExistsOnLayer('Mid Layer 3') OR ExistsOnLayer('Mid Layer 4') OR ExistsOnLayer('Mid Layer 5') OR ExistsOnLayer('Mid Layer 6') OR ExistsOnLayer('Mid Layer 7') OR ExistsOnLayer('Mid Layer 8') OR ExistsOnLayer('Mid Layer 9') OR ExistsOnLayer('Mid Layer 10')] p9: gap=0.125 ignorepadtopadclearanceinfootprint=FALSE
Clearance C_ClassNVtoAll_onOutside [InNetClass('NV') AND (ExistsOnLayer('Top Side') OR ExistsOnLayer('Bottom Side')) vs ExistsOnLayer('Top Side') OR ExistsOnLayer('Bottom Side')] p10: gap=0.125 ignorepadtopadclearanceinfootprint=FALSE
Clearance C_ClassNVtoAll_onMid [InNetClass('NV')  AND ( ExistsOnLayer('Mid Layer 1') OR ExistsOnLayer('Mid Layer 2') OR ExistsOnLayer('Mid Layer 3') OR ExistsOnLayer('Mid Layer 4') OR ExistsOnLayer('Mid Layer 5') OR ExistsOnLayer('Mid Layer 6') OR ExistsOnLayer('Mid Layer 7') OR ExistsOnLayer('Mid Layer 8') OR ExistsOnLayer('Mid Layer 9') OR ExistsOnLayer('Mid Layer 10') ) vs ExistsOnLayer('Mid Layer 1') OR ExistsOnLayer('Mid Layer 2') OR ExistsOnLayer('Mid Layer 3') OR ExistsOnLayer('Mid Layer 4') OR ExistsOnLayer('Mid Layer 5') OR ExistsOnLayer('Mid Layer 6') OR ExistsOnLayer('Mid Layer 7') OR ExistsOnLayer('Mid Layer 8') OR ExistsOnLayer('Mid Layer 9') OR ExistsOnLayer('Mid Layer 10')] p11: gap=0.125 ignorepadtopadclearanceinfootprint=FALSE
Clearance C_NoClasstoAll_onOutside [(ExistsOnLayer('Top Side') OR ExistsOnLayer('Bottom Side')) vs ExistsOnLayer('Top Side') OR ExistsOnLayer('Bottom Side')] p12: gap=0.125 ignorepadtopadclearanceinfootprint=FALSE
Clearance C_NoClasstoAll_onMid [( ExistsOnLayer('Mid Layer 1') OR ExistsOnLayer('Mid Layer 2') OR ExistsOnLayer('Mid Layer 3') OR ExistsOnLayer('Mid Layer 4') OR ExistsOnLayer('Mid Layer 5') OR ExistsOnLayer('Mid Layer 6') OR ExistsOnLayer('Mid Layer 7') OR ExistsOnLayer('Mid Layer 8') OR ExistsOnLayer('Mid Layer 9') OR ExistsOnLayer('Mid Layer 10') ) vs ExistsOnLayer('Mid Layer 1') OR ExistsOnLayer('Mid Layer 2') OR ExistsOnLayer('Mid Layer 3') OR ExistsOnLayer('Mid Layer 4') OR ExistsOnLayer('Mid Layer 5') OR ExistsOnLayer('Mid Layer 6') OR ExistsOnLayer('Mid Layer 7') OR ExistsOnLayer('Mid Layer 8') OR ExistsOnLayer('Mid Layer 9') OR ExistsOnLayer('Mid Layer 10')] p13: gap=0.125 ignorepadtopadclearanceinfootprint=FALSE
Clearance C_STEGKeepout [InComponent('STEG*') vs IsKeepout] p14: gap=0 ignorepadtopadclearanceinfootprint=FALSE
Clearance C_All [All] p15: gap=0.15 ignorepadtopadclearanceinfootprint=FALSE except(0: SMDPad-Hole THPad-Hole Via-Hole Fill-Hole Poly-Hole Region-Hole Text-Hole; 0.3: Arc-Hole Track-Hole)
ComponentClearance CC_TPMToTP [InComponent('TPM*') vs InComponent('TP*')] p1: gap=0 collisioncheckmode=3 verticalgap=0 showdistances=FALSE
ComponentClearance CC_BarcodeToAll [(ObjectKind = '3D Body') And (Identifier = 'Barcode')] p2: gap=0 collisioncheckmode=3 verticalgap=0 showdistances=FALSE donotcheckwithout3dbody=TRUE checkcomponentboundary=TRUE
ComponentClearance CC_Free3DBody [(ObjectKind = '3D Body') and not InComponent('*') vs (ObjectKind = '3D Body') and not InComponent('*')] p3: gap=0 collisioncheckmode=3 verticalgap=0 showdistances=FALSE
ComponentClearance CC_CMP8MMtoTP [InComponent('*')  and (AsMM(Height) >= 8.0) vs InComponent('TP*')] p4 off: gap=4 collisioncheckmode=3 verticalgap=4 showdistances=FALSE donotcheckwithout3dbody=TRUE checkcomponentboundary=TRUE
ComponentClearance CC_CMPtoTP [InComponent('*') vs InComponent('TP*')] p5: gap=0.5 collisioncheckmode=3 verticalgap=0.5 showdistances=FALSE donotcheckwithout3dbody=TRUE checkcomponentboundary=TRUE
ComponentClearance CC_AllToAll [All] p6: gap=0 collisioncheckmode=3 verticalgap=0 showdistances=FALSE checkcomponentboundary=TRUE
DiffPairsRouting DPR_All [All] p1: maxlimit=0.3 minlimit=0.2 mostfreqgap=0.2 toplayer_minwidth=0.2 toplayer_maxwidth=0.25 toplayer_prefwidth=0.2 midlayer1_minwidth=0.2 midlayer1_maxwidth=0.25 midlayer1_prefwidth=0.2 midlayer2_minwidth=0.2 midlayer2_maxwidth=0.25 midlayer2_prefwidth=0.2 midlayer3_minwidth=0.2 midlayer3_maxwidth=0.25 midlayer3_prefwidth=0.2 midlayer4_minwidth=0.2 midlayer4_maxwidth=0.25 midlayer4_prefwidth=0.2 midlayer5_minwidth=0.2 midlayer5_maxwidth=0.25 midlayer5_prefwidth=0.2 midlayer6_minwidth=0.2 midlayer6_maxwidth=0.25 midlayer6_prefwidth=0.2 bottomlayer_minwidth=0.2 bottomlayer_maxwidth=0.25 bottomlayer_prefwidth=0.2 maxuncoupledlength=12.7
FabricationTestPointUsage [All] p1: valid=2 allowmultiple=FALSE
FabricationTestpoint [All] p1: side=3 testpointundercomponent=TRUE minsize=0.1 maxsize=10 preferedsize=1 minholesize=0 maxholesize=10 preferedholesize=1 testpointgrid=0.025 allowsidetop=TRUE allowsidebottom=TRUE usegrid=FALSE gridtolerance=0
HoleSize HS_All [All] p1: absolutevalues=TRUE maxlimit=5 minlimit=0.125 maxpercent=80.000 minpercent=20.000
HoleToHoleClearance HtHC_MicroToMicro [IsMicroVia vs IsMicroVia] p1: gap=0.2 allowstackedmicrovias=TRUE
HoleToHoleClearance HtHC_MicroToBuried [IsMicroVia vs isBuriedVia] p2: gap=0.225 allowstackedmicrovias=FALSE
HoleToHoleClearance HtHC_ThruToBuried [IsThruVia vs isBuriedVia] p3: gap=0.4 allowstackedmicrovias=TRUE
HoleToHoleClearance HtHC_STEG [InComponent('STEG*') vs InComponent('STEG*')] p4: gap=0.1 allowstackedmicrovias=TRUE
HoleToHoleClearance HtHC_All [All] p5: gap=0.4 allowstackedmicrovias=TRUE
LayerPairs LP_All [All] p1: enforce=TRUE
MinimumSolderMaskSliver MSMS_All [All] p1: minsoldermaskwidth=0.1
NetAntennae NA_All [All] p1: netantennaetolerance=0
PasteMaskExpansion PME_All [All] p1: expansion=0
PolygonConnect PCS_Testpoint [Testpoint] p1: connectstyle=Direct reliefconductorwidth=0.254 reliefentries=4 polygonreliefangle="90 Angle" airgapwidth=0.254
PolygonConnect PCS_MountingHole [(InComponent('MH*'))] p2: connectstyle=Direct reliefconductorwidth=0.254 reliefentries=4 polygonreliefangle="90 Angle" airgapwidth=0.254
PolygonConnect PCS_MountingSpacer [(InComponent('MP*'))] p3: connectstyle=Direct reliefconductorwidth=0.254 reliefentries=4 polygonreliefangle="90 Angle" airgapwidth=0.254
PolygonConnect PCS_X300 [InComponent('X300')] p4: connectstyle=Direct reliefconductorwidth=0.2 reliefentries=4 polygonreliefangle="90 Angle" airgapwidth=0.2
PolygonConnect PCS_X400 [InComponent('X400a')] p5: connectstyle=Direct reliefconductorwidth=0.2 reliefentries=4 polygonreliefangle="90 Angle" airgapwidth=0.2
PolygonConnect PCS_D400 [InComponent('D400')] p6: connectstyle=Relief reliefconductorwidth=0.6 reliefentries=4 polygonreliefangle="90 Angle" airgapwidth=0.2
PolygonConnect PCS_L300-L302 [HasFootprint('INDDFN2_1200X1200X1020L255X500N')] p7: connectstyle=Direct reliefconductorwidth=0.2 reliefentries=4 polygonreliefangle="90 Angle" airgapwidth=0.2
PolygonConnect PCS_L400-L402 [HasFootprint('INDDFN2_800X800X420L232X630N')] p8: connectstyle=Direct reliefconductorwidth=0.2 reliefentries=4 polygonreliefangle="90 Angle" airgapwidth=0.2
PolygonConnect PCS_X2_GND [InComponent('X2') vs InNet('GND')] p9: connectstyle=Relief reliefconductorwidth=0.15 reliefentries=4 polygonreliefangle="90 Angle" airgapwidth=0.2
PolygonConnect PCS_X2 [InComponent('X2')] p10: connectstyle=Relief reliefconductorwidth=0.6 reliefentries=4 polygonreliefangle="90 Angle" airgapwidth=0.2
PolygonConnect PCS_X1_GND [InComponent('X1') vs InNet('GND')] p11: connectstyle=Relief reliefconductorwidth=0.375 reliefentries=4 polygonreliefangle="90 Angle" airgapwidth=0.2
PolygonConnect PCS_X1 [InComponent('X1')] p12: connectstyle=Relief reliefconductorwidth=0.5 reliefentries=4 polygonreliefangle="90 Angle" airgapwidth=0.2
PolygonConnect PCS_X16_GND [InComponent('X16') vs InNet('GND')] p13: connectstyle=Relief reliefconductorwidth=0.125 reliefentries=4 polygonreliefangle="90 Angle" airgapwidth=0.2
PolygonConnect PCS_X16 [InComponent('X16')] p14: connectstyle=Relief reliefconductorwidth=0.15 reliefentries=4 polygonreliefangle="90 Angle" airgapwidth=0.2
PolygonConnect PCS_X4_GND [InComponent('X4') vs InNet('GND')] p15: connectstyle=Relief reliefconductorwidth=0.125 reliefentries=4 polygonreliefangle="90 Angle" airgapwidth=0.2
PolygonConnect PCS_X4 [InComponent('X16')] p16: connectstyle=Relief reliefconductorwidth=0.15 reliefentries=4 polygonreliefangle="90 Angle" airgapwidth=0.2
PolygonConnect PCS_X3_SGND [InComponent('X3') vs InNet('SGND')] p17: connectstyle=Relief reliefconductorwidth=0.375 reliefentries=4 polygonreliefangle="90 Angle" airgapwidth=0.2
PolygonConnect PCS_X3 [InComponent('X3')] p18: connectstyle=Relief reliefconductorwidth=0.5 reliefentries=4 polygonreliefangle="90 Angle" airgapwidth=0.2
PolygonConnect PCS_ELKOs [HasFootprint('PANASONIC_F_VIB')] p19: connectstyle=Direct reliefconductorwidth=0.6 reliefentries=4 polygonreliefangle="90 Angle" airgapwidth=0.2
PolygonConnect PCS_SMAJ [HasFootprint('DIOM519X260X262L114X145N')] p20: connectstyle=Relief reliefconductorwidth=0.8 reliefentries=4 polygonreliefangle="90 Angle" airgapwidth=0.2
PolygonConnect PCS_SODFL [HasFootprint('SODFL359X170X143L65X95N')] p21: connectstyle=Relief reliefconductorwidth=0.6 reliefentries=4 polygonreliefangle="90 Angle" airgapwidth=0.2
PolygonConnect PCS_Fuse [HasFootprint('FUSC650X370X403L148N')] p22: connectstyle=Direct reliefconductorwidth=0.6 reliefentries=4 polygonreliefangle="90 Angle" airgapwidth=0.2
PolygonConnect PCS_X13 [HasFootprint('GTC_USB4115-03-C')] p23: connectstyle=Direct reliefconductorwidth=0.6 reliefentries=4 polygonreliefangle="90 Angle" airgapwidth=0.2
PolygonConnect PCS_DefaultComponents [InComponent('*')] p24: connectstyle=Relief reliefconductorwidth=0.2 reliefentries=4 polygonreliefangle="90 Angle" airgapwidth=0.2
PolygonConnect PCS_All [All] p25: connectstyle=Direct reliefconductorwidth=0.254 reliefentries=4 polygonreliefangle="90 Angle" airgapwidth=0.254
RoutingLayers RL_All [All] p1: top layer_v5=TRUE mid layer 1_v5=TRUE mid layer 2_v5=TRUE mid layer 3_v5=TRUE mid layer 4_v5=TRUE mid layer 5_v5=TRUE mid layer 6_v5=TRUE bottom layer_v5=TRUE
RoutingTopology RT_All [All] p1: topology=Shortest
RoutingVias RVS_MicroVia [IsMicroVia] p1: holewidth=0.125 width=0.35 viastyle="Through Hole" minholewidth=0.125 minwidth=0.35 maxholewidth=0.125 maxwidth=0.35
RoutingVias RVS_SkipVia [IsSkipVia] p2: holewidth=2 width=2 viastyle="Through Hole" minholewidth=2 minwidth=2 maxholewidth=2 maxwidth=2
RoutingVias RVS_BlindVia [IsBlindVia] p3: holewidth=2 width=2 viastyle="Through Hole" minholewidth=2 minwidth=2 maxholewidth=2 maxwidth=2
RoutingVias RVS_BuriedVia [IsBuriedVia] p4: holewidth=2 width=2 viastyle="Through Hole" minholewidth=2 minwidth=2 maxholewidth=2 maxwidth=2
RoutingVias RVS_ThruVia [IsThruVia] p5: holewidth=0.25 width=0.6 viastyle="Through Hole" minholewidth=0.25 minwidth=0.6 maxholewidth=0.25 maxwidth=0.6
SMDEntry SE_All [All] p1: side=TRUE corner=TRUE anyangle=TRUE
ShortCircuit S-C_All [All] p1: allowed=FALSE
SilkToSilkClearance StSC_All [All] p1: silktosilkclearance=0.25
SilkToSolderMaskClearance StSMC_Pad [IsPad] p1: minsilkscreentomaskgap=0.25 clearancetoexposedcopper=TRUE
SolderMaskExpansion SME_MicroVia [IsMicroVia] p1: expansion=0 istentingtop=TRUE soldermaskfromhole=TRUE
SolderMaskExpansion SME_BlindVia [IsBlindVia] p2: expansion=0 istentingtop=TRUE soldermaskfromhole=TRUE
SolderMaskExpansion SME_ThruVia [IsThruVia] p3: expansion=0.075 istentingtop=FALSE soldermaskfromhole=TRUE
SolderMaskExpansion SME_NPTH [(ObjectKind = 'Pad') AND (Layer = 'MultiLayer') AND (PadIsPlated = 'False')] p4: expansion=0.075 istentingtop=FALSE soldermaskfromhole=TRUE
SolderMaskExpansion SME_Check [All] p5 off: expansion=0.05 istentingtop=FALSE
SolderMaskExpansion SME_All [All] p6: expansion=0 istentingtop=FALSE
UnRoutedNet URN_All [All] p1: checkbadconnections=TRUE
UnpouredPolygon MP_All [All] p1:
Width W_onOutside_AND_onMidNexToOutside_uVia [ExistsOnLayer('Top Side') OR ExistsOnLayer('Bottom Side') OR ExistsOnLayer('Mid Layer 1') OR ExistsOnLayer('Mid Layer 6')] p1: maxlimit=4 minlimit=0.125 preferedwidth=0.15 minimp=50.000000 maximp=50.000000 favimp=50.000000 checkconnectedcopper=TRUE
Width W_onMid [ExistsOnLayer('Mid Layer 1') OR ExistsOnLayer('Mid Layer 2') OR ExistsOnLayer('Mid Layer 3') OR ExistsOnLayer('Mid Layer 4') OR ExistsOnLayer('Mid Layer 5') OR ExistsOnLayer('Mid Layer 6') OR ExistsOnLayer('Mid Layer 7') OR ExistsOnLayer('Mid Layer 8') OR ExistsOnLayer('Mid Layer 9') OR ExistsOnLayer('Mid Layer 10')] p2: maxlimit=4 minlimit=0.125 preferedwidth=0.15 minimp=50.000000 maximp=50.000000 favimp=50.000000 checkconnectedcopper=TRUE
11 further rules are at their usual default settings.

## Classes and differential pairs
net class HV: C_VDigIO C_VL C_VP C_W1 C_W2 C_W3 NetC303_1 NetC304_1 NetC305_1 U V VL VP W

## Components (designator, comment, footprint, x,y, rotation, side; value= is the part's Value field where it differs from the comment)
C200 "0402 100nF" CAPC100X50X70L25N 68.025,49.675 r90 bottom locked value=100nF
C201 "0402 100nF" CAPC100X50X70L25N 28.05,13.115 r90 bottom locked value=100nF
C202 "0603 100nF" CAPC160X80X100L35N 25.05,11.725 r0 top locked value=100nF
C203 "0402 100nF" CAPC100X50X70L25N 45.75,65.45 r90 bottom locked value=100nF
C204 "C0805C103KBRACAUTO" CAPC200X125X150L47N 6.275,11.6 r270 bottom locked value=10nF
C205 "C0805C103KBRACAUTO" CAPC200X125X150L47N 69.8,60.475 r90 bottom locked value=10nF
C206 "0603 100nF" CAPC160X80X100L35N 9.975,58.7 r180 top locked value=100nF
C207 "0402 100nF" CAPC100X50X70L25N 18.825,63.275 r90 bottom locked value=100nF
C208 "0402 100nF" CAPC100X50X70L25N 17.3,55.55 r90 bottom locked value=100nF
C209 "0402 100nF" CAPC100X50X70L25N 14.45,55.55 r270 bottom locked value=100nF
C210 "0402 100nF" CAPC100X50X70L25N 18.8,58.25 r90 bottom locked value=100nF
C211 "0402 100nF" CAPC100X50X70L25N 15.875,56 r180 bottom locked value=100nF
C212 "0402 100nF" CAPC100X50X70L25N 22.45,63.1 r270 bottom locked value=100nF
C300 "EEHZA1K220P" PANASONIC_F_VIB 27.4,45.1 r0 top locked value=22µF
C301 "EEHZA1K220P" PANASONIC_F_VIB 27.4,34.6 r90 top locked value=22µF
C302 "EEHZA1K220P" PANASONIC_F_VIB 27.4,24.1 r0 top locked value=22µF
C303 "0603 470p" CAPC160X80X100L35N 61.275,34.55 r90 top locked value=470pF
C304 "0603 470p" CAPC160X80X100L35N 61.275,49.05 r90 top locked value=470pF
C305 "0603 470p" CAPC160X80X100L35N 61.275,20.025 r90 top locked value=470pF
C306 "0603 220pF" CAPC160X80X100L35N 59.475,34.55 r90 top locked value=220pF
C307 "0603 220pF" CAPC160X80X100L35N 59.475,49.05 r90 top locked value=220pF
C308 "0603 220pF" CAPC160X80X100L35N 59.475,20.025 r90 top locked value=220pF
D200 "D12V0L1B2LP-7B" DIONPDFN2_102X60X60L25X50N 66.7,48.225 r0 bottom locked
D201 "1N4148WL2-TP" DIODFN2_102X60X60L25X50N 25.775,13.2 r90 top locked
D202 "EZAEG2A50AX" DIONPC105X53X43L26N 36.25,12.15 r270 top locked
D203 "EZAEG2A50AX" DIONPC105X53X43L26N 37.75,12.15 r270 top locked
D204 "1N4148WL2-TP" DIODFN2_102X60X60L25X50N 31.875,3.65 r90 bottom locked
D205 "1N4148WL2-TP" DIODFN2_102X60X60L25X50N 30.125,3.65 r90 bottom locked
D206 "SS110LW" SODFL359X170X143L65X95N 28.75,13.975 r0 top locked
D207 "SS110LW" SODFL359X170X143L65X95N 28.75,11.75 r0 top locked
D208 "PESD5V0L4UG" SOT23-5P65_210X110L28X20N 8,53.7 r90 bottom locked
D209 "EZAEG2A50AX" DIONPC105X53X43L26N 33.25,12.15 r270 top locked
D210 "EZAEG2A50AX" DIONPC105X53X43L26N 34.75,12.15 r270 top locked
D300 "SS110LW" SODFL359X170X143L65X95N 10,33.135 r180 top locked
D301 "SS110LW" SODFL359X170X143L65X95N 14,34.9 r90 top locked
D302 "SMAJ60A" DIOM519X260X262L114X145N 17.2,41.1 r90 top locked
D303 "SMAJ60A" DIOM519X260X262L114X145N 17.2,30.975 r270 top locked
DS200 "598-8010-107F" LEDSC80X160X90L45N_RED 16.6,23.6 r180 top
DS201 "598-8070-107F" LEDSC80X160X90L45N_GREEN 16.6,25 r180 top
F300 "0157010." FUSC650X370X403L148N 8.775,38 r0 top locked
FD200 "FDc80c160" FIDUCIAL_c80_c160 0.9,0.9 r90 top locked
FD201 "FDc80c160" FIDUCIAL_c80_c160 74.7,0.9 r90 bottom locked
FD202 "FDc80c160" FIDUCIAL_c80_c160 74.7,71.1 r90 top locked
FD203 "FDc80c160" FIDUCIAL_c80_c160 0.9,71.1 r90 bottom locked
L300 "7447709150" INDDFN2_1200X1200X1020L255X500N 51,38 r0 top locked value=15µH
L301 "7447709150" INDDFN2_1200X1200X1020L255X500N 51,52.5 r0 top locked value=15µH
L302 "7447709150" INDDFN2_1200X1200X1020L255X500N 51,23.5 r0 top locked value=15µH
LS200 "LAYERSTAIR 8 LAYER" 8LS400X50w/oLETTERS_KEEPOUT 65.65,0.775 r0 top locked
MH200 "MTGNPH400A900V8H40_Snap-In_Spacer" MTGNPH400A900V8H40_Snap-In_Spacer 5,5 r0 top locked
MH201 "MTGNPH400A900V8H40_Snap-In_Spacer" MTGNPH400A900V8H40_Snap-In_Spacer 70.6,5 r0 top locked
MH202 "MTGNPH400A900V8H40_Snap-In_Spacer" MTGNPH400A900V8H40_Snap-In_Spacer 70.6,67 r0 top locked
MH203 "MTGNPH400A900V8H40_Snap-In_Spacer" MTGNPH400A900V8H40_Snap-In_Spacer 5,67 r0 top locked
MH204 "MTGNPH220_NPTH" MTGNPH220 9.3,61.3 r90 top locked
MH205 "MTGNPH220_NPTH" MTGNPH220 57.6,6 r90 top locked
MP200 "973100365" WURTH_973100365 5,5 r225 bottom locked
MP201 "973100365" WURTH_973100365 70.6,5 r315 bottom locked
MP202 "973100365" WURTH_973100365 70.6,67 r45 bottom locked
MP203 "973100365" WURTH_973100365 5,67 r135 bottom locked
MP300 "9774040943" WURTH_9774040943_NPTH 37.7,18.5 r180 bottom locked
MP301 "9774040943" WURTH_9774040943_NPTH 18.9,50.3 r180 bottom locked
MP302 "9774040243" WURTH_9774040243_NPTH 18.9,18.5 r180 bottom locked
MP303 "9774040243" WURTH_9774040243_NPTH 37.7,50.3 r180 bottom locked
Q200 "VNS1NV04DP-E" SOIC8P127_490X599X175L83X41N 31,8.4 r0 bottom locked
R200 "0402 47R" RESC100X52X40L22N 68.5,47.35 r180 bottom locked value=47
R202 "0402 2.2k" RESC100X52X40L22N 32.9,3.8 r270 bottom locked value=2.2k
R203 "0402 2.2k" RESC100X52X40L22N 29.1,3.8 r270 bottom locked value=2.2k
R204 "0402 220R" RESC100X52X40L22N 32.45,12.575 r0 bottom locked value=220
R205 "0402 220R" RESC100X52X40L22N 29.875,12.575 r0 bottom locked value=220
R206 "1206 2M 500V" RESC320X160X90L47N 4.05,12.2 r270 bottom locked value=2M
R207 "0402 5.1k" RESC100X52X40L22N 6.075,58.425 r180 top locked value=5.1k
R208 "0402 5.1k" RESC100X52X40L22N 9.925,51.575 r0 top locked value=5.1k
R209 "0805 120R" RESC200X125X84L35N 50.95,11.5 r90 top locked value=120
R210 "0402 0" RESC100X52X40L22N 53.475,10.85 r270 top locked value=0
R211 "0402 680R" RESC100X52X40L22N 16.15,23.6 r180 bottom locked value=680
R212 "0402 680R" RESC100X52X40L22N 16.15,25 r180 bottom locked value=680
R213 "0402 10k" RESC100X52X40L22N 41.475,54.875 r90 bottom value=10k
R214 "0402 10k" RESC100X52X40L22N 32.175,17.7 r180 bottom value=10k
R215 "0402 10k" RESC100X52X40L22N 27.35,17.7 r0 bottom value=10k
R309 "0805 270R" RESC200X125X84L35N 60.375,32.15 r0 top locked value=270
R310 "0805 270R" RESC200X125X84L35N 60.375,46.65 r0 top locked value=270
R311 "0805 270R" RESC200X125X84L35N 60.375,17.625 r0 top locked value=270
R324 "0402 10k" RESC100X52X40L22N 40.65,28.775 r180 bottom locked value=10k
STEG200 "Steg400X90_7Hole" Steg_400X90_7Hole 18,0 r0 top locked
STEG201 "Steg400X90_7Hole" Steg_400X90_7Hole 57.575,0 r0 top locked
STEG202 "Steg400X90_7Hole" Steg_400X90_7Hole 75.6,36 r90 top locked
STEG203 "Steg400X90_7Hole" Steg_400X90_7Hole 57.575,72 r180 top locked
STEG204 "Steg400X90_7Hole" Steg_400X90_7Hole 18,72 r180 top locked
STEG205 "Steg400X90_7Hole" Steg_400X90_7Hole 0,36 r270 top locked
SW1 "DHN-08F-T-V" SOIC16P127_1139X671X151L61X41N 48.2,5.9 r0 top locked
SYM200 "BARCODE_EMS500x500" BARCODE_EMS_500x500 51.075,38.175 r180 bottom locked
SYM201 "ESD500X450" ESD_copper_small 61.75,4 r0 top locked
SYM202 "ESD500X450" ESD_copper_small 62.25,9.025 r180 bottom locked
SYM203 "PCB_MARKING1200x600" MARKING_PCB_1200x600 49.95,24.025 r180 bottom locked
TP200 "TPc120" TESTPOINT_c120 4.2,39.3 r90 bottom locked
TP201 "TPc120" TESTPOINT_c120 2.3,38.3 r90 bottom locked
TP202 "TPc120" TESTPOINT_c120 65.05,50.475 r0 bottom locked
TP203 "TPc120" TESTPOINT_c120 64.775,47.95 r0 bottom locked
TP204 "TPc120" TESTPOINT_c120 7.8,33.1 r90 bottom locked
TP205 "TPc120" TESTPOINT_c120 5.9,32.1 r90 bottom locked
TP206 "TPc120" TESTPOINT_c120 73.15,51.025 r0 bottom locked
TP207 "TPc120" TESTPOINT_c120 62.5,38 r90 bottom locked
TP208 "TPc120" TESTPOINT_c120 62.5,52.5 r90 bottom locked
TP209 "TPc120" TESTPOINT_c120 62.5,23.5 r90 bottom locked
TP211 "TPc120" TESTPOINT_c120 22.025,60.125 r90 bottom locked
TP212 "TPc120" TESTPOINT_c120 24.425,62 r90 bottom locked
TP213 "TPc120" TESTPOINT_c120 72.95,46 r0 bottom locked
TP214 "TPc120" TESTPOINT_c120 74.325,49.025 r0 bottom locked
TP215 "TPc120" TESTPOINT_c120 70,45.675 r0 bottom locked
TP216 "TPc120" TESTPOINT_c120 70.4,52.275 r0 bottom locked
TP217 "TPc120" TESTPOINT_c120 66.8,52.275 r0 bottom locked
TP218 "TPc120" TESTPOINT_c120 70.4,54.825 r0 bottom locked
TP219 "TPc120" TESTPOINT_c120 66.8,54.825 r0 bottom locked
TP220 "TPc120" TESTPOINT_c120 66.8,57.475 r0 bottom locked
TP221 "TPc120" TESTPOINT_c120 49.3,67.8 r270 bottom locked
TP222 "TPc120" TESTPOINT_c120 47.4,67.8 r270 bottom locked
TP223 "TPc120" TESTPOINT_c120 74.275,17.7 r180 bottom locked
TP224 "TPc120" TESTPOINT_c120 34.8,6 r90 bottom locked
TP225 "TPc120" TESTPOINT_c120 27.2,6 r90 bottom locked
TP226 "TPc120" TESTPOINT_c120 27.3,11.1 r90 bottom locked
TP227 "TPc120" TESTPOINT_c120 74.275,14.7 r180 bottom locked
TP228 "TPc120" TESTPOINT_c120 45.5,67.5 r270 bottom locked
TP229 "TPc120" TESTPOINT_c120 25.9,7.5 r90 bottom locked
TP230 "TPc120" TESTPOINT_c120 29.5,62.2 r90 bottom locked
TP231 "TPc120" TESTPOINT_c120 30.8,63.6 r90 bottom locked
TP232 "TPc120" TESTPOINT_c120 32.5,62.2 r90 bottom locked
TP233 "TPc120" TESTPOINT_c120 33.8,63.6 r90 bottom locked
TP234 "TPc120" TESTPOINT_c120 35.1,62.2 r90 bottom locked
TP235 "TPc120" TESTPOINT_c120 34.8,15.09 r90 bottom locked
TP236 "TPc120" TESTPOINT_c120 27.2,15.09 r90 bottom locked
TP237 "TPc120" TESTPOINT_c120 37,62.2 r90 bottom locked
TP238 "TPc120" TESTPOINT_c120 32.3,64.8 r90 bottom locked
TP239 "TPc120" TESTPOINT_c120 42.6,10.2 r90 bottom locked
TP240 "TPc120" TESTPOINT_c120 50,14.7 r90 bottom locked
TP241 "TPc120" TESTPOINT_c120 50,12.8 r90 bottom locked
TP242 "TPc120" TESTPOINT_c120 48.3,13.8 r90 bottom locked
TP243 "TPc120" TESTPOINT_c120 44.9,9 r90 bottom locked
TP244 "TPc120" TESTPOINT_c120 74.275,21.7 r180 bottom locked
TP245 "TPc120" TESTPOINT_c120 46.3,6.5 r90 bottom locked
TP246 "TPc120" TESTPOINT_c120 7,56.2 r0 bottom locked
TP247 "TPc120" TESTPOINT_c120 9.9,58.7 r0 bottom locked
TP248 "TPc120" TESTPOINT_c120 47.3,9 r90 bottom locked
TP249 "TPc120" TESTPOINT_c120 6.7,58.8 r0 bottom locked
TP250 "TPc120" TESTPOINT_c120 49.2,9 r90 bottom locked
TP251 "TPc120" TESTPOINT_c120 10.1,50.9 r0 bottom locked
TP252 "TPc120" TESTPOINT_c120 5.9,50.9 r0 bottom locked
TP253 "TPc120" TESTPOINT_c120 50.1,6.5 r90 bottom locked
TP254 "TPc120" TESTPOINT_c120 8.9,56.2 r0 bottom locked
TP255 "TPc120" TESTPOINT_c120 51.4,9 r90 bottom locked
TP256 "TPc120" TESTPOINT_c120 54.7,7.7 r90 bottom locked
TP257 "TPc120" TESTPOINT_c120 53.8,10.2 r90 bottom locked
TP258 "TPc120" TESTPOINT_c120 15.7,22 r90 bottom locked
TP259 "TPc120" TESTPOINT_c120 60,70 r270 bottom locked
TP260 "TPc120" TESTPOINT_c120 57.3,70 r270 bottom locked
TP261 "TPc120" TESTPOINT_c120 15.7,26.6 r90 bottom
TP262 "TPc120" TESTPOINT_c120 14.7,65.5 r90 bottom locked
TP263 "TPc120" TESTPOINT_c120 17.7,65.5 r90 bottom locked
TP264 "TPc120" TESTPOINT_c120 16.2,66.7 r90 bottom locked
TP265 "TPc120" TESTPOINT_c120 48.3,69.5 r270 bottom locked
TP266 "TPc120" TESTPOINT_c120 65,14.7 r180 bottom locked
TP267 "TPc120" TESTPOINT_c120 65,17.7 r180 bottom locked
TP268 "TPc120" TESTPOINT_c120 65,20.7 r180 bottom locked
TP269 "TPc120" TESTPOINT_c120 38.2,12 r180 bottom locked
TP270 "TPc120" TESTPOINT_c120 36.8,9.6 r180 bottom locked
TP271 "TPc120" TESTPOINT_c120 35.1,12 r180 bottom locked
TP272 "TPc120" TESTPOINT_c120 34.9,9.1 r180 bottom locked
TP300 "TPc120" TESTPOINT_c120 42.8,38 r90 bottom locked
TP301 "TPc120" TESTPOINT_c120 42.8,41.9 r90 bottom locked
TP302 "TPc120" TESTPOINT_c120 42.8,34.1 r90 bottom locked
TP304 "TPc120" TESTPOINT_c120 44.7,38 r90 bottom locked
TP309 "TPc120" TESTPOINT_c120 41.8,31.05 r90 bottom locked
TP313 "TPc120" TESTPOINT_c120 14.5,30 r90 bottom locked
TP314 "TPc120" TESTPOINT_c120 14.3,42.4 r90 bottom locked
TP315 "TPc120" TESTPOINT_c120 14.5,32.9 r90 bottom locked
TP316 "TPc120" TESTPOINT_c120 14.3,39.4 r90 bottom locked
U200 "SN74LVC1G17DCK" SOT23-5P65_210X110L28X20N 70.275,49.475 r270 bottom locked
U201 "SN74AHCT1G00DCKR" SOT23-5P65_210X110L28X20N 32.35,15.09 r0 bottom locked
U202 "SN74AHCT1G00DCKR" SOT23-5P65_210X110L28X20N 29.65,15.09 r0 bottom locked
U203 "MAX202IPW" SOP16P65_500X640X120L83X24N 15.55,60.2 r180 bottom locked
X1 "39281023" MOLEX_460150202 8,45 r270 top locked
X2 "39281023" MOLEX_460150202 8,28 r270 top locked
X3 "39281043" MOLEX_460150402 68.375,32.45 r90 top locked
X4 "430450612" "MOLEX_ 430450612" 69.575,17.7 r270 top locked
X5 "52601-S10-8LF" AMPHENOL_52601-S10-8LF 68.6,50.75 r90 top locked
X7 "5025840860" MOLEX_5025840860 32.5,5.4 r180 top locked
X8 "5025840760" MOLEX_5025840760 33.8,66.6 r0 top locked
X10 "RS232" MOLEX_5025840560 17.7,66.6 r0 top locked
X11 "5025840460" MOLEX_5025840460 5.4,16.8 r90 top locked
X12 "5025840460" MOLEX_5025840460 16.8,5.4 r180 top locked
X13 "USB4115-03-C" GTC_USB4115-03-C 8,55 r0 top locked
X16 "430450212" "MOLEX_ 430450212" 57.3,65.2 r0 top locked
X200 "AXT410124" PANASONIC_AXT410124 47.8,69.1 r180 top locked
X300 "SS4-40-3.00-L-D-K-TR" SAMTEC_SS4-40-3.00-L-D-K-TR 29,38 r0 bottom locked

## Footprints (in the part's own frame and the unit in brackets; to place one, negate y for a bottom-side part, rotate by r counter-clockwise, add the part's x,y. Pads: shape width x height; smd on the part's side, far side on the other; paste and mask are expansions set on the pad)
8LS400X50w/oLETTERS_KEEPOUT [mm] "Layerstair 8 Layers, 4.00 mm X 0.5 mm, without Letters and KeepOut"
  Top Side region: -2,-0.25 -1.5,-0.25 -1.5,0.25 -2,0.25
  Mid Layer 1 region: -1.5,-0.25 -1,-0.25 -1,0.25 -1.5,0.25
  Mid Layer 2 region: -1,-0.25 -0.5,-0.25 -0.5,0.25 -1,0.25
  Mid Layer 3 region: -0.5,-0.25 0,-0.25 0,0.25 -0.5,0.25
  Mid Layer 6 region: 1.5,0.25 1,0.25 1,-0.25 1.5,-0.25
  Mid Layer 4 region: 0.5,0.25 0,0.25 0,-0.25 0.5,-0.25
  Mid Layer 5 region: 1,0.25 0.5,0.25 0.5,-0.25 1,-0.25
  Bottom Side region: 1.5,-0.25 2,-0.25 2,0.25 1.5,0.25
AMPHENOL_52601-S10-8LF [mm] "Header, 2.54mm Pitch, Dual Row, SMT, Vertical, 10 Circuits"
  rrect50% 1.27x3.18 smd: 1(-5.08,-2.73) 2(-5.08,2.73) 3(-2.54,-2.73) 4(-2.54,2.73) 5(0,-2.73) 6(0,2.73) 7(2.54,-2.73) 8(2.54,2.73) 9(5.08,-2.73) 10(5.08,2.73)
  body extent -10.05,-4.38 10.05,4.38, height 12.76
BARCODE_EMS_500x500 [mm] "Barcode EMS, 5.00 mm L X 5.00 mm W X 0.00 mm H body"
  Top Side keep-out region: -2.5,2.5 2.5,2.5 2.5,-2.5 -2.5,-2.5
  body extent -2.5,-2.5 2.5,2.5, height 0.01
CAPC100X50X70L25N [mm] "Capacitor, Chip; 1.00 mm L X 0.50 mm W X 0.70 mm H body"
  rrect49% 0.63x0.61 smd: 1(-0.45,0) 2(0.45,0)
  body extent -0.55,-0.3 0.55,0.3, height 0.7
CAPC160X80X100L35N [mm] "Capacitor, Chip; 1.60 mm L X 0.80 mm W X 1.00 mm H body"
  rrect50% 0.96x1.02 smd: 1(-0.725,0) 2(0.725,0)
  body extent -0.9,-0.5 0.9,0.5, height 1
CAPC200X125X150L47N [mm] "Capacitor, Chip; 2.00 mm L X 1.25 mm W X 1.50 mm H body"
  rrect42% 1.18x1.47 smd: 1(-0.865,0) 2(0.865,0)
  body extent -1.15,-0.72 1.15,0.72, height 1.5
DIODFN2_102X60X60L25X50N [mm] "Diode, Dual Flat No-Lead (DFN 2 Pin); 2 pin, 1.025 mm L X 0.60 mm W X 0.60 mm H body"
  rect 0.36x0.63 smd: 1(-0.325,0) 2(0.325,0)
  body extent -0.55,-0.35 0.55,0.35, height 0.6
DIOM519X260X262L114X145N [mm] "Diode, Molded Body; 4.295 mm L X 2.605 mm W X 2.62 mm H body"
  rrect30% 2.277x1.665 smd: 1(-2.16,0) 2(2.16,0)
  body extent -2.8,-1.46 2.8,1.46, height 2.62
DIONPC105X53X43L26N [mm] "Diode, Non-polarized, Chip; 1.05 mm L X 0.53 mm W X 0.43 mm H Body"
  rrect50% 0.65x0.625 smd: 1(-0.485,0) 2(0.485,0)
  body extent -0.6,-0.3 0.6,0.31, height 0.43
DIONPDFN2_102X60X60L25X50N [mm] "Diode, Non-polarized, Dual Flat No-Lead, 2 pin; 1.025 mm L X 0.60 mm W X 0.60 mm H body"
  rect 0.28x0.549 smd: 1(-0.325,0) 2(0.325,0)
  body extent -0.55,-0.35 0.55,0.35, height 0.6
ESD_copper_small [mm] "ESD-Sign copper 5.0x4.5mm"
  Top Side region: 1157 vertices and 0 holes, not listed, extent -1.517,-1.207 1.291,0.001
  Top Side region: 575 vertices and 0 holes, not listed, extent 0.39,-0.947 1.392,0.012
  Top Side region: 602 vertices and 0 holes, not listed, extent -0.696,0.176 0.501,1.443
  Top Side lines w0.3: -2.242,-1.599 0.003,2.289 2.247,-1.599 -2.242,-1.599
FIDUCIAL_c80_c160 [mm] "Fiducial, Global; 0 pin"
  round 0.8 smd paste-0.8 mask+0.4: 1(0,0)
  Top Side keep-out circle w0.025: c0,0 r0.8
FUSC650X370X403L148N [mm] "Fuse, Chip; 6.50 mm L X 3.70 mm W X 4.03 mm H body"
  rrect21% 2.4x3 smd: 1(-2.43,0) 2(2.43,0)
  body extent -3.35,-1.91 3.35,1.91, height 4.03
GTC_USB4115-03-C [mm] "USB Type C, SHLD, 24poles"
  round 0.66 hole 0.66 unplated mask+0.15: 0(-3.75,0)
  round 0.58 hole 0.58 unplated mask+0.15: 0(3.75,0)
  rect 0.3x0.79 smd: A1(-2.75,0.805) A2(-2.25,0.805) A11(2.25,0.805) A12(2.75,0.805) B1(2.75,-0.805) B2(2.25,-0.805) B11(-2.25,-0.805) B12(-2.75,-0.805)
  rect 0.3x0.85 smd: A3(-1.75,0.835) A4(-1.25,0.835) A5(-0.75,0.835) A6(-0.25,0.835) A7(0.25,0.835) A8(0.75,0.835) A9(1.25,0.835) A10(1.75,0.835) B3(1.75,-0.835) B4(1.25,-0.835) B5(0.75,-0.835) B6(0.25,-0.835) B7(-0.25,-0.835) B8(-0.75,-0.835) B9(-1.25,-0.835) B10(-1.75,-0.835)
  round 1.1 hole 0.7: S1(-2.4,2.15) S2(-2.4,-2.15) S3(2.4,-2.15) S4(2.4,2.15)
  Top Side keep-out region: 0.8,-2.5 -0.8,-2.5 -0.8,-1.8 0.8,-1.8
  Top Side keep-out region: 0.8,1.8 -0.8,1.8 -0.8,2.5 0.8,2.5
  body extent -4.47,-2.3 4.47,2.3, height 9.25
INDDFN2_1200X1200X1020L255X500N [mm] "Inductor, Dual Flat No-Lead, 2 pin; 12.00 mm L X 12.00 mm W X 10.20 mm H body"
  rect 3.035x5.215 smd: 1(-4.85,0) 2(4.85,0)
  body extent -6.3,-6.25 6.3,6.25, height 10.2
LEDSC80X160X90L45N_GREEN [mm] "LED, Side Concave Package; 2 pin, 0.80 mm L X 1.60 mm W X 0.90 mm H body, green"
  rrect50% 0.94x0.749 smd: 1(-0.745,0) 2(0.745,0)
  body extent -0.85,-0.45 0.85,0.45, height 0.9
LEDSC80X160X90L45N_RED [mm] "LED, Side Concave Package; 2 pin, 0.80 mm L X 1.60 mm W X 0.90 mm H body, red"
  rrect50% 0.94x0.749 smd: 1(-0.745,0) 2(0.745,0)
  body extent -0.85,-0.45 0.85,0.45, height 0.9
MARKING_PCB_1200x600 [mm] "Marking PCB, 12.00 mm L X 6.00 mm W X 0.00 mm H body"
  Top Side keep-out region: -6,3 6,3 6,-3 -6,-3
  body extent -6,-3 6,3, height 0.02
MOLEX_460150202 [mm] "Header, Vertical Shrouded, 4.20 mm row X 5.50 mm column pitch; 1.00 mm lead width, 2 pins, 2 rows, 1 pin per row, 5.40 mm L X 9.60 mm W X 12.80 mm H body"
  rrect50% 2.33x2.33 hole 1.4: 1(0,2.75)
  round 2.33 hole 1.4: 2(0,-2.75)
  body extent -3.1,-6 3.1,5, height 12.81
MOLEX_460150402 [mm] "Header, Vertical Shrouded, 4.20 mm row X 5.50 mm column pitch; 1.00 mm lead width, 4 pins, 2 rows, 2 pins per row, 9.60 mm L X 9.60 mm W X 12.80 mm H body"
  rrect50% 2.33x2.33 hole 1.4: 1(-2.1,2.55)
  round 2.33 hole 1.4: 2(2.1,2.55) 3(-2.1,-2.95) 4(2.1,-2.95)
  body extent -5.2,-6.2 5.2,4.8, height 12.8
MOLEX_5025840460 [mm] "Header, 1.5mm pitch, 4 position, top entry, SMT"
  rrect50% 1.8x3.3 smd: 0(-4.85,1.275) 0(4.85,1.275)
  rrect50% 0.8x2.4 smd: 1(-2.25,-3.775) 2(-0.75,-3.775) 3(0.75,-3.775) 4(2.25,-3.775)
  Top Side keep-out region: 1.225,-4.024 1.775,-4.024 1.775,-1.424 1.225,-1.424
  Top Side keep-out region: -0.275,-4.024 0.275,-4.024 0.275,-1.424 -0.275,-1.424
  Top Side keep-out region: -1.775,-4.024 -1.225,-4.024 -1.225,-1.424 -1.775,-1.424
  Top Side keep-out region: -5.55,-4.024 -2.725,-4.024 -2.725,-1.424 -5.55,-1.424
  Top Side keep-out region: -0.91,0.869 0.91,0.869 0.91,3.429 -0.91,3.429
  Top Side keep-out region: -1.9,3.429 -3.9,3.429 -3.9,1.379 -1.9,1.379
  Top Side keep-out region: 5.55,-1.425 2.725,-1.425 2.725,-4.025 5.55,-4.025
  Top Side keep-out region: 1.9,1.379 3.9,1.379 3.9,3.429 1.9,3.429
  Top Side keep-out lines w0.05: -2.7,-1.449 2.7,-1.449
  body extent -5.15,-4.22 5.15,3.18, height 7.3
MOLEX_5025840560 [mm] "Header, 1.50mm Pitch, Receptacle, Single Row, SMT, Vertical, 5 Circuits"
  rrect50% 1.8x3.3 smd: 0(-5.6,1.275) 0(5.6,1.275)
  rrect50% 0.8x2.4 smd: 1(-3,-3.775) 2(-1.5,-3.775) 3(0,-3.775) 4(1.5,-3.775) 5(3,-3.775)
  Top Side keep-out region: -0.91,0.869 0.91,0.869 0.91,3.429 -0.91,3.429
  Top Side keep-out region: -6.3,-4.024 -3.45,-4.024 -3.45,-1.424 -6.3,-1.424
  Top Side keep-out region: -2.55,-4.024 -1.95,-4.024 -1.95,-1.424 -2.55,-1.424
  Top Side keep-out region: -2.65,3.429 -4.65,3.429 -4.65,1.379 -2.65,1.379
  Top Side keep-out region: 6.3,-1.425 3.45,-1.425 3.45,-4.025 6.3,-4.025
  Top Side keep-out region: 2.65,1.379 4.65,1.379 4.65,3.429 2.65,3.429
  Top Side keep-out region: -1.05,-4.024 -0.45,-4.024 -0.45,-1.424 -1.05,-1.424
  Top Side keep-out region: 0.45,-4.024 1.05,-4.024 1.05,-1.424 0.45,-1.424
  Top Side keep-out region: 1.95,-4.024 2.55,-4.024 2.55,-1.424 1.95,-1.424
  Top Side keep-out lines w0.05: -3.45,-1.449 3.45,-1.449
  body extent -5.9,-4.22 5.9,3.18, height 7.3
MOLEX_5025840760 [mm] "Connector, 1.50mm Pitch, Receptacle, Single Row, SMT, Vertical, 7 Circuits"
  rrect50% 1.8x3.3 smd: 0(-7.1,1.275) 0(7.1,1.275)
  rrect50% 0.8x2.4 smd: 1(-4.5,-3.775) 2(-3,-3.775) 3(-1.5,-3.775) 4(0,-3.775) 5(1.5,-3.775) 6(3,-3.775) 7(4.5,-3.775)
  Top Side keep-out region: 4.149,1.378 6.149,1.378 6.149,3.428 4.149,3.428
  Top Side keep-out region: 7.8,-1.424 4.95,-1.424 4.95,-4.024 7.8,-4.024
  Top Side keep-out region: 3.45,-4.024 4.05,-4.024 4.05,-1.424 3.45,-1.424
  Top Side keep-out region: 1.95,-4.024 2.55,-4.024 2.55,-1.424 1.95,-1.424
  Top Side keep-out region: 0.45,-4.024 1.05,-4.024 1.05,-1.424 0.45,-1.424
  Top Side keep-out region: -1.05,-4.024 -0.45,-4.024 -0.45,-1.424 -1.05,-1.424
  Top Side keep-out region: -2.55,-4.024 -1.95,-4.024 -1.95,-1.424 -2.55,-1.424
  Top Side keep-out region: -4.15,3.428 -6.15,3.428 -6.15,1.378 -4.15,1.378
  Top Side keep-out region: -4.05,-4.024 -3.45,-4.024 -3.45,-1.424 -4.05,-1.424
  Top Side keep-out region: -7.8,-4.024 -4.95,-4.024 -4.95,-1.424 -7.8,-1.424
  Top Side keep-out region: -0.91,0.869 0.91,0.869 0.91,3.429 -0.91,3.429
  Top Side keep-out lines w0.05: -4.95,-1.449 4.95,-1.449
  body extent -7.4,-4.22 7.4,3.18, height 7.3
MOLEX_5025840860 [mm] "Connector, 1.50mm Pitch, Receptacle, Single Row, SMT, Vertical, 8 Pins"
  rrect50% 1.8x3.3 smd: 0(-7.85,1.275) 0(7.85,1.275)
  rrect50% 0.8x2.4 smd: 1(-5.25,-3.775) 2(-3.75,-3.775) 3(-2.25,-3.775) 4(-0.75,-3.775) 5(0.75,-3.775) 6(2.25,-3.775) 7(3.75,-3.775) 8(5.25,-3.775)
  Top Side keep-out region: -0.91,0.869 0.91,0.869 0.91,3.429 -0.91,3.429
  Top Side keep-out region: -4.9,3.429 -6.9,3.429 -6.9,1.379 -4.9,1.379
  Top Side keep-out region: -4.8,-4.024 -4.2,-4.024 -4.2,-1.424 -4.8,-1.424
  Top Side keep-out region: -8.55,-4.024 -5.7,-4.024 -5.7,-1.424 -8.55,-1.424
  Top Side keep-out region: -3.3,-4.024 -2.7,-4.024 -2.7,-1.424 -3.3,-1.424
  Top Side keep-out region: -1.8,-4.024 -1.2,-4.024 -1.2,-1.424 -1.8,-1.424
  Top Side keep-out region: -0.3,-4.024 0.3,-4.024 0.3,-1.424 -0.3,-1.424
  Top Side keep-out region: 1.2,-4.024 1.8,-4.024 1.8,-1.424 1.2,-1.424
  Top Side keep-out region: 2.7,-4.024 3.3,-4.024 3.3,-1.424 2.7,-1.424
  Top Side keep-out region: 4.2,-4.024 4.8,-4.024 4.8,-1.424 4.2,-1.424
  Top Side keep-out region: 4.9,1.379 6.9,1.379 6.9,3.429 4.9,3.429
  Top Side keep-out region: 8.55,-1.425 5.7,-1.425 5.7,-4.025 8.55,-4.025
  Top Side keep-out lines w0.05: 5.7,-1.449 -5.7,-1.449
  body extent -8.15,-4.22 8.15,3.18, height 7.3
"MOLEX_ 430450212" [mm] "Micro-Fit 3.0 Vertical Header, 3.00mm Pitch, Dual Row, 2 Circuits, with PCB Polarizing Peg, Black"
  round 0 hole 1.1 unplated mask+0.15: 0(-3,2.44) 0(3,2.44)
  rrect50% 1.8x1.8 hole 1.1: 1(0,-1.5)
  round 1.8 hole 1.1: 2(0,1.5)
  body extent -3.57,-3.94 3.57,4.83, height 9.95
"MOLEX_ 430450612" [mm] "Micro-Fit 3.0 Vertical Header, 3.00mm Pitch, Dual Row, 6 Circuits, with PCB Polarizing Peg, Black"
  round 0 hole 1.1 unplated mask+0.15: 0(-6,2.44) 0(6,2.44)
  rrect50% 1.8x1.8 hole 1.1: 1(3,-1.5)
  round 1.8 hole 1.1: 2(0,-1.5) 3(-3,-1.5) 4(3,1.5) 5(0,1.5) 6(-3,1.5)
  body extent -6.58,-3.97 6.58,4.8, height 9.95
MTGNPH220 [mm] "Mounting Hole, Non-Plated; 0.00 mm Clearance, 2.20 mm Hole"
  round 0 hole 2.2 unplated paste-2539.97 mask+0.15: 1(0,0)
MTGNPH400A900V8H40_Snap-In_Spacer [mm] "Mounting Hole, Non-Plated; 9.00 mm Clearance, 4.00 mm Hole (with 8 vias), for 4mm Dia. Snap-In Spacer"
  round 0 hole 4 unplated mask+4.5: 1(0,0)
  round 0.6 hole 0.4: 2(0,3.47) 3(-2.45,2.45) 4(-3.47,0) 5(-2.45,-2.45) 6(0,-3.47) 7(2.45,-2.45) 8(3.47,0) 9(2.45,2.45)
  Multi-Layer region: -2.45,0 -4.5,0 -4.483,0.392 -4.432,0.781 -4.347,1.165 -4.229,1.539 -4.078,1.902 -3.897,2.25 -3.686,2.581 -3.447,2.893 -3.182,3.182 -2.893,3.447 -2.581,3.686 -2.25,3.897 -1.902,4.078 -1.539,4.229 -1.165,4.347 -0.781,4.432 -0.392,4.483 0,4.5 0.392,4.483 0.781,4.432 1.165,4.347 1.539,4.229 1.902,4.078 2.25,3.897 2.581,3.686 2.893,3.447 3.182,3.182 3.447,2.893 3.686,2.581 3.897,2.25 4.078,1.902 4.229,1.539 4.347,1.165 4.432,0.781 4.483,0.392 4.5,0 4.483,-0.392 4.432,-0.781 4.347,-1.165 4.229,-1.539 4.078,-1.902 3.897,-2.25 3.686,-2.581 3.447,-2.893 3.182,-3.182 2.893,-3.447 2.581,-3.686 2.25,-3.897 1.902,-4.078 1.539,-4.229 1.165,-4.347 0.781,-4.432 0.392,-4.483 0,-4.5 -0.392,-4.483 -0.781,-4.432 -1.165,-4.347 -1.539,-4.229 -1.902,-4.078 -2.25,-3.897 -2.581,-3.686 -2.893,-3.447 -3.182,-3.182 -3.447,-2.893 -3.686,-2.581 -3.897,-2.25 -4.078,-1.902 -4.229,-1.539 -4.347,-1.165 -4.432,-0.781 -4.483,-0.392 -4.5,0 -2.45,0 -2.441,-0.213 -2.413,-0.425 -2.367,-0.634 -2.302,-0.838 -2.221,-1.035 -2.122,-1.225 -2.007,-1.405 -1.877,-1.575 -1.732,-1.732 -1.575,-1.877 -1.405,-2.007 -1.225,-2.122 -1.035,-2.221 -0.838,-2.302 -0.634,-2.367 -0.425,-2.413 -0.213,-2.441 0,-2.45 0.213,-2.441 0.425,-2.413 0.634,-2.367 0.838,-2.302 1.035,-2.221 1.225,-2.122 1.405,-2.007 1.575,-1.877 1.732,-1.732 1.877,-1.575 2.007,-1.405 2.122,-1.225 2.221,-1.035 2.302,-0.838 2.367,-0.634 2.413,-0.425 2.441,-0.213 2.45,0 2.441,0.213 2.413,0.425 2.367,0.634 2.302,0.838 2.221,1.035 2.122,1.225 2.007,1.405 1.877,1.575 1.732,1.732 1.575,1.877 1.405,2.007 1.225,2.122 1.035,2.221 0.838,2.302 0.634,2.367 0.425,2.413 0.213,2.441 0,2.45 -0.213,2.441 -0.425,2.413 -0.634,2.367 -0.838,2.302 -1.035,2.221 -1.225,2.122 -1.405,2.007 -1.575,1.877 -1.732,1.732 -1.877,1.575 -2.007,1.405 -2.122,1.225 -2.221,1.035 -2.302,0.838 -2.367,0.634 -2.413,0.425 -2.441,0.213 -2.45,0
PANASONIC_AXT410124 [mm] "0.40 mm pitch; 10 pin, 3.90 mm L X 1.45 mm W X 1.24 mm H body"
  rrect50% 0.45x0.5 smd: 0(-1.6,-0.575) 0(-1.6,0.575) 0(1.6,-0.575) 0(1.6,0.575)
  rrect50% 0.2x0.77 smd: 1(-0.8,-1.045) 2(-0.8,1.045) 3(-0.4,-1.045) 4(-0.4,1.045) 5(0,-1.045) 6(0,1.045) 7(0.4,-1.045) 8(0.4,1.045) 9(0.8,-1.045) 10(0.8,1.045)
  Top Side keep-out region: -0.983,0.335 0.983,0.335 0.983,0.61 -0.983,0.61
  Top Side keep-out region: -0.983,-0.61 0.983,-0.61 0.983,-0.335 -0.983,-0.335
  body extent -1.95,-1.17 1.95,1.18, height 1.24
PANASONIC_F_VIB [mil] "Capacitor, Aluminum Electrolytic; F Panasonic Vibration proof 8.30 mm L X 8.30 mm W X 10.50 mm H Body"
  round 1 smd: 1(-137.8,0) 2(137.8,0)
  Top Side region: 206.69,39.37 214.37,37.65 220.81,33.11 225.03,26.46 226.37,18.7 226.38,18.7 226.38,-18.7 225.03,-26.46 220.81,-33.11 214.37,-37.65 206.69,-39.37 206.69,-39.37 143.7,-39.37 143.7,-79.72 142.72,-84.62 139.95,-88.77 135.8,-91.55 130.9,-92.52 130.9,-92.52 105.31,-92.52 100.42,-91.55 96.26,-88.77 93.49,-84.62 92.52,-79.72 92.52,-79.72 92.52,-39.37 69.88,-39.37 62.12,-38.02 55.47,-33.81 50.93,-27.37 49.21,-19.68 49.21,-19.68 49.21,19.69 50.93,27.37 55.47,33.81 62.12,38.02 69.88,39.37 69.88,39.37 92.52,39.37 92.52,79.72 93.49,84.62 96.26,88.77 100.42,91.55 105.31,92.52 105.31,92.52 130.9,92.52 135.8,91.55 139.95,88.77 142.72,84.62 143.7,79.72 143.7,79.72 143.7,39.37
  Top Side region: -206.69,-39.37 -214.38,-37.65 -220.82,-33.11 -225.03,-26.46 -226.38,-18.7 -226.38,-18.7 -226.38,18.7 -223.92,28.86 -216.72,36.42 -206.69,39.37 -206.69,39.37 -143.7,39.37 -143.7,79.72 -142.73,84.62 -139.95,88.77 -135.8,91.55 -130.91,92.52 -130.91,92.52 -105.32,92.52 -100.42,91.55 -96.27,88.77 -93.49,84.62 -92.52,79.72 -92.52,79.72 -92.52,39.37 -69.88,39.37 -62.12,38.02 -55.47,33.81 -50.94,27.37 -49.21,19.68 -49.21,19.69 -49.21,-19.68 -50.94,-27.37 -55.47,-33.81 -62.12,-38.02 -69.88,-39.37 -69.88,-39.37 -92.52,-39.37 -92.52,-79.72 -93.49,-84.62 -96.27,-88.77 -100.42,-91.55 -105.32,-92.52 -105.32,-92.52 -130.91,-92.52 -135.8,-91.55 -139.95,-88.77 -142.73,-84.62 -143.7,-79.72 -143.7,-79.72 -143.7,-39.37
  body extent -191,-163 191,163, height 413
RESC100X52X40L22N [mm] "Resistor, Chip; 1.00 mm L X 0.525 mm W X 0.40 mm H body"
  rrect51% 0.59x0.62 smd: 1(-0.47,0) 2(0.47,0)
  body extent -0.55,-0.3 0.55,0.3, height 0.4
RESC200X125X84L35N [mm] "Resistor, Chip; 2.00 mm L X 1.25 mm W X 0.84 mm H body"
  rrect50% 0.96x1.47 smd: 1(-0.925,0) 2(0.925,0)
  body extent -1.1,-0.72 1.1,0.73, height 0.84
RESC320X160X90L47N [mm] "Resistor, Chip; 3.20 mm L X 1.60 mm W X 0.90 mm H body"
  rrect43% 1.15x1.82 smd: 1(-1.48,0) 2(1.48,0)
  body extent -1.7,-0.9 1.7,0.9, height 0.9
SAMTEC_SS4-40-3.00-L-D-K-TR [mm] "SS4 0.40 mm Micro Blade & Beam Ultra Fine Pitch Socket, 80 poles"
  rrect50% 0.2x0.95 smd: 1(7.8,2.325) 2(7.8,-2.325) 3(7.4,2.325) 4(7.4,-2.325) 5(7,2.325) 6(7,-2.325) 7(6.6,2.325) 8(6.6,-2.325) 9(6.2,2.325) 10(6.2,-2.325) 11(5.8,2.325) 12(5.8,-2.325) 13(5.4,2.325) 14(5.4,-2.325) 15(5,2.325) 16(5,-2.325) 17(4.6,2.325) 18(4.6,-2.325) 19(4.2,2.325) 20(4.2,-2.325) 21(3.8,2.325) 22(3.8,-2.325) 23(3.4,2.325) 24(3.4,-2.325) 25(3,2.325) 26(3,-2.325) 27(2.6,2.325) 28(2.6,-2.325) 29(2.2,2.325) 30(2.2,-2.325) 31(1.8,2.325) 32(1.8,-2.325) 33(1.4,2.325) 34(1.4,-2.325) 35(1,2.325) 36(1,-2.325) 37(0.6,2.325) 38(0.6,-2.325) 39(0.2,2.325) 40(0.2,-2.325) 41(-0.2,2.325) 42(-0.2,-2.325) 43(-0.6,2.325) 44(-0.6,-2.325) 45(-1,2.325) 46(-1,-2.325) 47(-1.4,2.325) 48(-1.4,-2.325) 49(-1.8,2.325) 50(-1.8,-2.325) 51(-2.2,2.325) 52(-2.2,-2.325) 53(-2.6,2.325) 54(-2.6,-2.325) 55(-3,2.325) 56(-3,-2.325) 57(-3.4,2.325) 58(-3.4,-2.325) 59(-3.8,2.325) 60(-3.8,-2.325) 61(-4.2,2.325) 62(-4.2,-2.325) 63(-4.6,2.325) 64(-4.6,-2.325) 65(-5,2.325) 66(-5,-2.325) 67(-5.4,2.325) 68(-5.4,-2.325) 69(-5.8,2.325) 70(-5.8,-2.325) 71(-6.2,2.325) 72(-6.2,-2.325) 73(-6.6,2.325) 74(-6.6,-2.325) 75(-7,2.325) 76(-7,-2.325) 77(-7.4,2.325) 78(-7.4,-2.325) 79(-7.8,2.325) 80(-7.8,-2.325)
  body extent -9.56,-2.5 9.98,2.5, height 3.5
SODFL359X170X143L65X95N [mm] "Diode, Small Outline Diode Flat Lead (SODFL); 2.70 mm L X 1.70 mm W X 1.43 mm H body"
  rrect42% 1.2x1.21 smd: 1(-1.505,0) 2(1.505,0)
  body extent -1.9,-0.95 1.9,0.95, height 1.43
SOIC8P127_490X599X175L83X41N [mm] "Small Outline IC (SOIC), 1.27 mm pitch; 8 pin, 4.90 mm L X 3.90 mm W X 1.75 mm H body"
  rrect52% 0.66x2.07 smd: 1(-1.905,-2.42) 2(-0.635,-2.42) 3(0.635,-2.42) 4(1.905,-2.42) 5(1.905,2.42) 6(0.635,2.42) 7(-0.635,2.42) 8(-1.905,2.42)
  body extent -2.5,-3.1 2.5,3.1, height 1.75
SOIC16P127_1139X671X151L61X41N [mm] "DIP8-SMD-Small, 1.27 mm pitch; 16 pin, 11.39 mm L X 4.50 mm W X 1.51 mm H Body"
  rrect50% 0.634x1.501 smd: 1(-4.445,-3.007) 2(-3.175,-3.007) 3(-1.905,-3.007) 4(-0.635,-3.007) 5(0.635,-3.007) 6(1.905,-3.007) 7(3.175,-3.007) 8(4.445,-3.007) 9(4.445,3.007) 10(3.175,3.007) 11(1.905,3.007) 12(0.635,3.007) 13(-0.635,3.007) 14(-1.905,3.007) 15(-3.175,3.007) 16(-4.445,3.007)
  body extent -5.69,-3.35 5.7,3.35, height 1.55
SOP16P65_500X640X120L83X24N [mm] "Small Outline Pkg (SOP), 0.65 mm pitch; 16 pin, 5.00 mm L X 4.40 mm W X 1.20 mm H body"
  rrect51% 0.39x1.77 smd: 1(-2.275,-2.625) 2(-1.625,-2.625) 3(-0.975,-2.625) 4(-0.325,-2.625) 5(0.325,-2.625) 6(0.975,-2.625) 7(1.625,-2.625) 8(2.275,-2.625) 9(2.275,2.625) 10(1.625,2.625) 11(0.975,2.625) 12(0.325,2.625) 13(-0.325,2.625) 14(-0.975,2.625) 15(-1.625,2.625) 16(-2.275,2.625)
  body extent -2.55,-3.3 2.55,3.3, height 1.2
SOT23-5P65_210X110L28X20N [mm] "Small Outline Transistor (SOT23), 0.65 mm pitch; 5 pin, 2.025 mm L X 1.25 mm W X 1.10 mm H body"
  rrect49% 0.37x1.04 smd: 1(-0.65,-0.935) 2(0,-0.935) 3(0.65,-0.935) 4(0.65,0.935) 5(-0.65,0.935)
  body extent -1.12,-1.2 1.12,1.2, height 1.1
Steg_400X90_7Hole [mm] "Steg; 4.00 mm L X 0.90 mm W, 7 Hole"
  round 0 hole 0.35 unplated mask+0.15: 0(-1.5,0) 0(-1,0) 0(-0.5,0) 0(0,0) 0(0.5,0) 0(1,0) 0(1.5,0)
  Keep-Out Layer lines w0.05: -1.95,0 cw(c-1.5,0) -1.5,0.45 1.5,0.45 cw(c1.5,0) 1.95,0
TESTPOINT_c120 [mm] "Test Point; 1 pin, 1.20 mm D X 0.00 mm H body"
  round 1.2 smd paste-2: 1(0,0)
  body extent -0.6,-0.6 0.6,0.6, height 0.01
WURTH_973100365 [mm] "WA-SNTI Plastic Spacer Stud, D=4.0mm, L=10mm, M3, SW=6"
  body extent -3,-3.46 3,3.46, height 10.01
WURTH_9774040243_NPTH [mm] "WA-SMST SMT Steel Spacer with internal Thread M2, L=4mm"
  round 0 hole 3 unplated paste-2539.97 mask+1.25: 0(0,0)
  round 0.85 smd paste-5 mask+0.102: 1(2.225,0)
  Multi-Layer lines w0.85: 2.225,0 cw(c0,0) -2.225,0 cw(c0,0) 2.225,0
  body extent -2.17,-2.16 2.17,2.16, height 4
